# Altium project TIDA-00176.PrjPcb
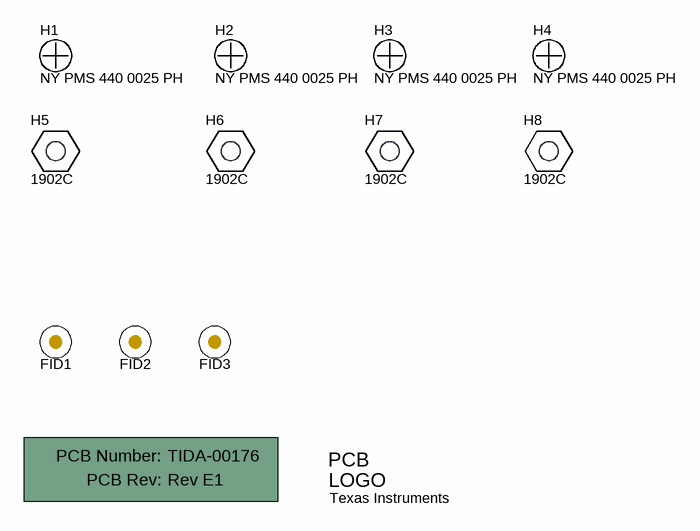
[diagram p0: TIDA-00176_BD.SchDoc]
CopyrightYear: 2015; EVM_Orderable: N/A; PCB_Layout: Stauder; PCB_Rev: Rev E1; PRJ_Customer: Public Release; PRJ_Engineer: Stauder/Pizzolante/Staebler; PRJ_Number: TIDA-00176; PRJ_Title: Interface to a SinCos Position Encoder; SCH_Rev: E1; TechSupport: http://www.ti.com/support; TID: 00176
4 sheets, 235 parts. Net scope: global (net labels, ports and power ports of the same name join across sheets).
Board file: TID.PcbDoc
Sheets:
  TIDA-00176_BD.SchDoc
  TIDA-00176_PS.SchDoc
  TIDA-00176_SCHS.SchDoc
  TIDA-00176_SCLS.SchDoc

## Sheet TIDA-00176_BD.SchDoc
size 431 x 279 mm; Date: Not shown in title block; ApprovedBy: Not shown in title block; CheckedBy: Not shown in title block; Author: Not shown in title block; CompanyName: Not shown in title block; Engineer: Not shown in title block; Organization: Not shown in title block; Address1: Not shown in title block; Address2: Not shown in title block; Address3: Not shown in title block; Address4: Not shown in title block; DocumentNumber: 1; Revision: Use project parameter SCH_Rev; SheetNumber: 3; SheetTotal: 3; PageSetup: Record=PageOptions¦CenterHorizontal=True¦CenterVertical=True¦PrintScale=1.00¦XCorrection=1.00¦YCorrection=1.00¦PrintKind=0¦BorderSize=5000000¦LeftOffset=0¦BottomOffset=0¦Orientation=2¦PaperLength=1000¦PaperWidth=1000¦Scale=100¦PaperSource=15¦PrintQuality=600¦MediaType=1¦DitherType=10¦PaperKind=Letter¦PrintScaleMode=1

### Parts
!PCB1  Printed Circuit Board  (value not drawn)  (mechanical)
FID1  Fiducial  [Fiducial10-20]  (value not drawn)
FID2  Fiducial  [Fiducial10-20]  (value not drawn)
FID3  Fiducial  [Fiducial10-20]  (value not drawn)
H1  NY PMS 440 0025 PH  [NY PMS 440 0025 PH]
H2  NY PMS 440 0025 PH  [NY PMS 440 0025 PH]
H3  NY PMS 440 0025 PH  [NY PMS 440 0025 PH]
H4  NY PMS 440 0025 PH  [NY PMS 440 0025 PH]
H5  1902C  [Keystone_1902C]
H6  1902C  [Keystone_1902C]
H7  1902C  [Keystone_1902C]
H8  1902C  [Keystone_1902C]
Logo1  Texas Instruments  [TI_Stacked_Overlay_Small]  (no BOM)

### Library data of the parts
!PCB1 = PCB: Manufacturer: Any; PartNumber: TIDA-00176; SymbolCreator: a0412235
FID1-FID3 = Fiducial: Fiducial mark.  There is nothing to buy or mount.; SymbolCreator: codlsc
H1-H4 = NY PMS 440 0025 PH: Machine Screw, Round, #4-40 x 1/4, Nylon, Philips panhead; Manufacturer: B&F Fastener Supply; CompType: Hardware; SymbolCreator: codlsc; U/M: EA
H5-H8 = 1902C: Standoff, Hex, 0.5"L #4-40 Nylon; Manufacturer: Keystone; CompType: Hardware
Logo1 = TI_Logo: Texas Instrument Corporate Signature; SymbolCreator: a0412235

## Sheet TIDA-00176_PS.SchDoc
size 431 x 279 mm; Date: Not shown in title block; ApprovedBy: Not shown in title block; CheckedBy: Not shown in title block; Author: Not shown in title block; CompanyName: Not shown in title block; Engineer: Not shown in title block; Organization: Not shown in title block; Address1: Not shown in title block; Address2: Not shown in title block; Address3: Not shown in title block; Address4: Not shown in title block; DocumentNumber: 1; Revision: Use project parameter SCH_Rev; SheetNumber: 2; SheetTotal: 3; PageSetup: Record=PageOptions¦CenterHorizontal=True¦CenterVertical=True¦PrintScale=0.66¦XCorrection=1.00¦YCorrection=1.00¦PrintKind=0¦BorderSize=5000000¦LeftOffset=0¦BottomOffset=0¦Orientation=2¦PaperLength=2970¦PaperWidth=2100¦Scale=100¦PaperSource=7¦PrintQuality=600¦MediaType=1¦DitherType=10¦PrintScaleMode=1¦PaperKind=A4¦PaperIndex=9
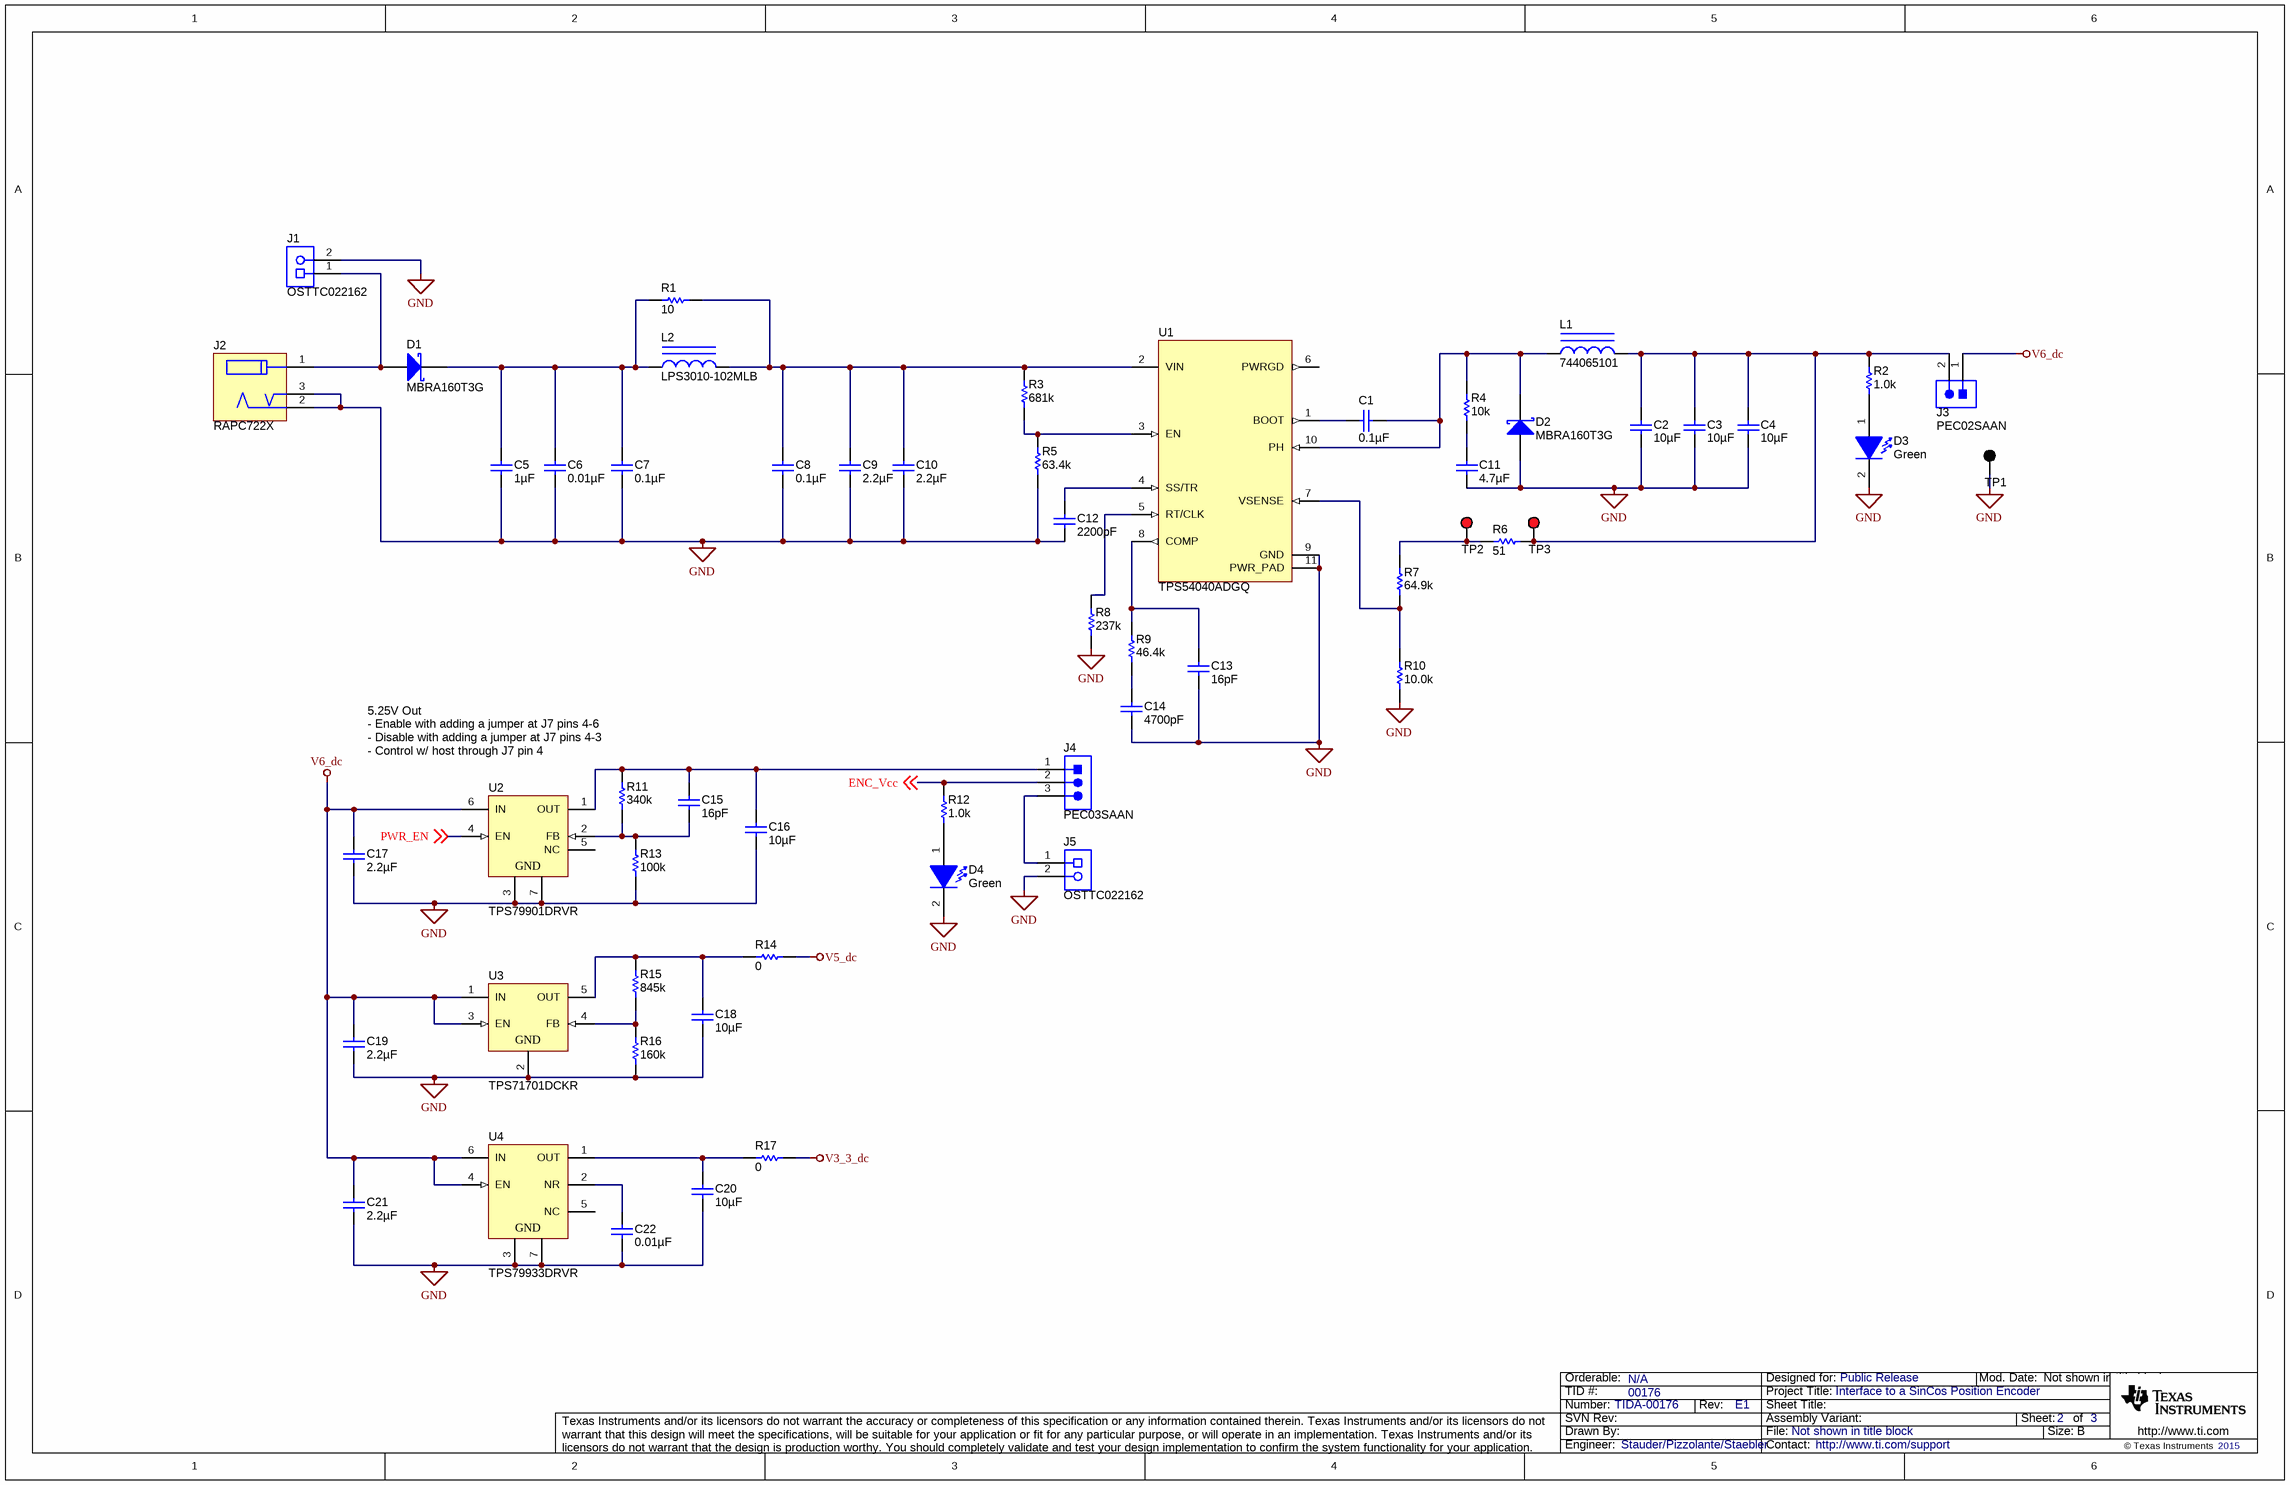
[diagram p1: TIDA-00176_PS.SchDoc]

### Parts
C1  ValueDisplayed: 0.1µF  [0603]  (hidden comment: GRM188R71H104KA93D)
C2  ValueDisplayed: 10µF  [1206_190]  (hidden comment: CGA5L3X5R1H106K160AB)
C3  ValueDisplayed: 10µF  [1206_190]  (hidden comment: CGA5L3X5R1H106K160AB)
C4  ValueDisplayed: 10µF  [1206_190]  (hidden comment: CGA5L3X5R1H106K160AB)
C5  ValueDisplayed: 1µF  [0805_HV]  (hidden comment: GRM21BR71H105KA12L)
C6  ValueDisplayed: 0.01µF  [0805_HV]  (hidden comment: GRM216R71H103KA01D)
C7  ValueDisplayed: 0.1µF  [0603]  (hidden comment: GRM188R71H104KA93D)
C8  ValueDisplayed: 0.1µF  [0603]  (hidden comment: GRM188R71H104KA93D)
C9  ValueDisplayed: 2.2µF  [1206]  (hidden comment: GRM31CR61H225KA88L)
C10  ValueDisplayed: 2.2µF  [1206]  (hidden comment: GRM31CR61H225KA88L)
C11  ValueDisplayed: 4.7µF  [0805_HV]  (hidden comment: C2012X5R1H475K125AB)
C12  ValueDisplayed: 2200pF  [0402]  (hidden comment: GRM155R61C222KA01D)
C13  ValueDisplayed: 16pF  [0402]  (hidden comment: GRM1555C1H160JA01D)
C14  ValueDisplayed: 4700pF  [0402]  (hidden comment: GRM155R71C472KA01D)
C15  ValueDisplayed: 16pF  [0402]  (hidden comment: GRM1555C1H160JA01D)
C16  ValueDisplayed: 10µF  [0805_HV]  (hidden comment: GRM219R61C106KA73D)
C17  ValueDisplayed: 2.2µF  [0603]  (hidden comment: GRM188R61C225KE15D)
C18  ValueDisplayed: 10µF  [0805_HV]  (hidden comment: GRM219R61C106KA73D)
C19  ValueDisplayed: 2.2µF  [0603]  (hidden comment: GRM188R61C225KE15D)
C20  ValueDisplayed: 10µF  [0805_HV]  (hidden comment: GRM219R61C106KA73D)
C21  ValueDisplayed: 2.2µF  [0603]  (hidden comment: GRM188R61C225KE15D)
C22  ValueDisplayed: 0.01µF  [0603]  (hidden comment: GRM188R71C103KA01D)
D1  MBRA160T3G  [SMA]
D2  MBRA160T3G  [SMA]
D3  value Green  [LG L29K_GREEN]  (hidden comment: LG L29K-G2J1-24-Z)
D4  value Green  [LG L29K_GREEN]  (hidden comment: LG L29K-G2J1-24-Z)
J1  OSTTC022162  [On-Shore_OSTTC022162]
J2  RAPC722X  [CONN_RAPC722X]
J3  PEC02SAAN  [CONN_PEC02SAAN]
J4  PEC03SAAN  [CONN_PEC03SAAN]
J5  OSTTC022162  [On-Shore_OSTTC022162]
L1  744065101  [WE-TPC-XLH2]
L2  LPS3010-102MLB  [LPS3010]
R1  value 10  [0603]  (hidden comment: CRCW060310R0JNEAHP)
R2  ValueDisplayed: 1.0k  [0402]  (hidden comment: CRCW04021K00JNED)
R3  ValueDisplayed: 681k  [0402]  (hidden comment: CRCW0402681KFKED)
R4  value 10k  [0805_HV]  (hidden comment: CRCW080510K0JNEA)
R5  ValueDisplayed: 63.4k  [0402]  (hidden comment: CRCW040263K4FKED)
R6  value 51  [0603]  (hidden comment: CRCW060351R0JNEA)
R7  ValueDisplayed: 64.9k  [0402]  (hidden comment: CRCW040264K9FKED)
R8  ValueDisplayed: 237k  [0402]  (hidden comment: CRCW0402237KFKED)
R9  ValueDisplayed: 46.4k  [0402]  (hidden comment: CRCW040246K4FKED)
R10  ValueDisplayed: 10.0k  [0402]  (hidden comment: CRCW040210K0FKED)
R11  ValueDisplayed: 340k  [0402]  (hidden comment: CRCW0402340KFKED)
R12  ValueDisplayed: 1.0k  [0402]  (hidden comment: CRCW04021K00JNED)
R13  ValueDisplayed: 100k  [0402]  (hidden comment: CRCW0402100KJNED)
R14  ValueDisplayed: 0  [0402]  (hidden comment: CRCW04020000Z0ED)
R15  ValueDisplayed: 845k  [0402]  (hidden comment: CRCW0402845KFKED)
R16  ValueDisplayed: 160k  [0402]  (hidden comment: CRCW0402160KJNED)
R17  ValueDisplayed: 0  [0402]  (hidden comment: CRCW04020000Z0ED)
TP1  5001  [Keystone5001]  (value not drawn)
TP2  5000  [Keystone5000]  (value not drawn)
TP3  5000  [Keystone5000]  (value not drawn)
U1  TPS54040ADGQ  [DGQ0010D_N]
U2  TPS79901DRVR  [DRV0006A]
U3  TPS71701DCKR  [DCK0005A_N]
U4  TPS79933DRVR  [DRV0006A]

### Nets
GND: C2.2 C3.2 C4.2 C5.2 C6.2 C7.2 C8.2 C9.2 C10.2 C11.2 C12.2 C13.2 C14.2 C16.2 C17.2 C18.2 C19.2 C20.2 C21.2 C22.2 D2.2(A) D3.2(K) D4.2(K) J1.2 J2.2 J2.3 J5.2 R5.1 R8.1 R10.1 R13.1 R16.1 TP1.1 U1.9(GND) U1.11(PWR_PAD) U2.3(GND) U2.7(GND) U3.2(GND) U4.3(GND) U4.7(GND)
V3_3_dc: R17.2
V5_dc: R14.2
V6_dc: C17.1 C19.1 C21.1 J3.1 U2.6(IN) U3.1(IN) U3.3(EN) U4.4(EN) U4.6(IN)
ENC_Vcc: J4.2 R12.2 ; off-sheet ENC_Vcc
PWR_EN: U2.4(EN) ; off-sheet PWR_EN
NetC1_1: C1.1 D2.1(K) L1.1 R4.2 U1.10(PH)
NetC1_2: C1.2 U1.1(BOOT)
NetC2_1: C2.1 C3.1 C4.1 J3.2 L1.2 R2.2 R6.1 TP3.1
NetC5_1: C5.1 C6.1 C7.1 D1.1(K) L2.1 R1.1
NetC8_1: C8.1 C9.1 C10.1 L2.2 R1.2 R3.2 U1.2(VIN)
NetC11_1: C11.1 R4.1
NetC12_1: C12.1 U1.4(SS/TR)
NetC13_1: C13.1 R9.2 U1.8(COMP)
NetC14_1: C14.1 R9.1
NetC15_1: C15.1 C16.1 J4.1 R11.2 U2.1(OUT)
NetC15_2: C15.2 R11.1 R13.2 U2.2(FB)
NetC18_1: C18.1 R14.1 R15.2 U3.5(OUT)
NetC20_1: C20.1 R17.1 U4.1(OUT)
NetC22_1: C22.1 U4.2(NR)
NetD1_2: D1.2(A) J1.1 J2.1
NetD3_1: D3.1(A) R2.1
NetD4_1: D4.1(A) R12.1
NetJ4_3: J4.3 J5.1
NetR3_1: R3.1 R5.2 U1.3(EN)
NetR6_2: R6.2 R7.2 TP2.1
NetR7_1: R7.1 R10.2 U1.7(VSENSE)
NetR8_2: R8.2 U1.5(RT/CLK)
NetR15_1: R15.1 R16.2 U3.4(FB)

Not connected (* = marked no-connect by the designer): U1 6(PWRGD); U2 5(NC); U4 5(NC)

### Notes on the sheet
- (near R11) 5.25V Out
  - Enable with adding a jumper at J7 pins 4-6
  - Disable with adding a jumper at J7 pins 4-3
  - Control w/ host through J7 pin 4

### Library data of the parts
C1 C7 C8 = GRM188R71H104KA93D: CAP, CERM, 0.1 µF, 50 V, +/- 10%, X7R, 0603; Manufacturer: MuRata; Polarized: N; CompType: Capacitor; Value: 0.1uF; U/M: EA; Cap_F: 0.0000001; Tolerance_%: 10; Value1: Unknown; VDC_V: 50; Value2: 50V; TaMin_C: -55; TaMax_C: 125
C2-C4 = CGA5L3X5R1H106K160AB: CAP, CERM, 10 µF, 50 V, +/- 10%, X5R, 1206_190; Manufacturer: TDK; Polarized: N; CompType: Capacitor; Value: 10uF; U/M: EA; Cap_F: 0.00001; Tolerance_%: 10; Value1: Unknown; VDC_V: 50; Value2: 50V; TaMin_C: -55; TaMax_C: 85
C5 = GRM21BR71H105KA12L: CAP, CERM, 1 µF, 50 V, +/- 10%, X7R, 0805; Manufacturer: MuRata; Polarized: N; CompType: Capacitor; Value: 1uF; U/M: EA; Cap_F: 0.000001; Tolerance_%: 10; Value1: Unknown; VDC_V: 50; Value2: 50V; TaMin_C: -55; TaMax_C: 125; Cap_Case: 0805
C6 = GRM216R71H103KA01D: CAP, CERM, 0.01 µF, 50 V, +/- 10%, X7R, 0805; Manufacturer: MuRata; Polarized: N; CompType: Capacitor; Value: 0.01uF; U/M: EA; Cap_F: 0.00000001; Tolerance_%: 10; Value1: Unknown; VDC_V: 50; Value2: 50V; TaMin_C: -55; TaMax_C: 125; Cap_Case: 0805
C9 C10 = GRM31CR61H225KA88L: CAP, CERM, 2.2uF, 50V, +/-10%, X5R, 1206; Manufacturer: MuRata; Polarized: N; CompType: Capacitor; U/M: EA; Cap_F: 0.0000022; Tolerance_%: 10; Value1: Unknown; VDC_V: 50; TaMin_C: -55; TaMax_C: 85
C11 = C2012X5R1H475K125AB: CAP, CERM, 4.7 µF, 50 V, +/- 10%, X5R, 0805; Manufacturer: TDK; Polarized: N; CompType: Capacitor; Value: 4.7uF; U/M: EA; Cap_F: 0.0000047; Tolerance_%: 10; Value1: Unknown; VDC_V: 50; Value2: 50V; TaMin_C: -55; TaMax_C: 85; Cap_Case: 0805
C12 = GRM155R61C222KA01D: CAP, CERM, 2200 pF, 16 V, +/- 10%, X5R, 0402; Manufacturer: MuRata; Polarized: N; CompType: Capacitor; Value: 2200pF; U/M: EA; Cap_F: 0.0000000022; Tolerance_%: 10; Value1: Unknown; VDC_V: 16; Value2: 16V; TaMin_C: -55; TaMax_C: 85
C13 C15 = GRM1555C1H160JA01D: CAP, CERM, 16 pF, 50 V, +/- 5%, C0G/NP0, 0402; Manufacturer: MuRata; Polarized: N; CompType: Capacitor; Value: 16pF; U/M: EA; Cap_F: 0.000000000016; Tolerance_%: 5; Value1: Unknown; VDC_V: 50; Value2: 50V; TaMin_C: -55; TaMax_C: 125
C14 = GRM155R71C472KA01D: CAP, CERM, 4700 pF, 16 V, +/- 10%, X7R, 0402; Manufacturer: MuRata; Polarized: N; CompType: Capacitor; Value: 4700pF; U/M: EA; Cap_F: 0.0000000047; Tolerance_%: 10; Value1: Unknown; VDC_V: 16; Value2: 16V; TaMin_C: -55; TaMax_C: 125
C16 C18 C20 = GRM219R61C106KA73D: CAP, CERM, 10 µF, 16 V, +/- 10%, X5R, 0805; Manufacturer: MuRata; Polarized: N; CompType: Capacitor; Value: 10uF; U/M: EA; Cap_F: 0.00001; Tolerance_%: 10; Value1: Unknown; VDC_V: 16; Value2: 16V; TaMin_C: -55; TaMax_C: 85; Cap_Case: 0805
C17 C19 C21 = GRM188R61C225KE15D: CAP, CERM, 2.2 µF, 16 V, +/- 10%, X5R, 0603; Manufacturer: MuRata; Polarized: N; CompType: Capacitor; Value: 2.2uF; U/M: EA; Cap_F: 0.0000022; Tolerance_%: 10; Value1: Unknown; VDC_V: 16; Value2: 16V; TaMin_C: -55; TaMax_C: 85
C22 = GRM188R71C103KA01D: CAP, CERM, 0.01 µF, 16 V, +/- 10%, X7R, 0603; Manufacturer: MuRata; Polarized: N; CompType: Capacitor; Value: 0.01uF; U/M: EA; Cap_F: 0.00000001; Tolerance_%: 10; Value1: Unknown; VDC_V: 16; Value2: 16V; TaMin_C: -55; TaMax_C: 125
D1 D2 = MBRA160T3G: Diode, Schottky, 60V, 1A, SMA; Manufacturer: ON Semiconductor; U/M: EA; Vf_V: 0.51; Value2: 0.51V; Io_A: 1; Vr_V: 60; TJmax_C: 150; RJC_CperW: 35
D3 D4 = LG L29K-G2J1-24-Z: LED, Green, SMD; Manufacturer: OSRAM; Vf_V: 1.7; Value2: 1.7V; Io_A: 0.002; Tjmax_C: 110; Value1: W; U/M: EA
J1 J5 = OSTTC022162: Terminal Block, 2-pole, 200mil, TH; Manufacturer: On-Shore Technology; SymbolCreator: a0412235; U/M: EA
J2 = RAPC722X: Power Jack, mini, 2.1mm OD, R/A, TH; Manufacturer: Switchcraft; SymbolCreator: a0799628; U/M: EA
J3 = PEC02SAAN: Header, 100mil, 2x1, Tin, TH; Manufacturer: Sullins Connector Solutions; SymbolCreator: a0412235; U/M: EA
J4 = PEC03SAAN: Header, 100mil, 3x1, Tin, TH; Manufacturer: Sullins Connector Solutions; SymbolCreator: a0799628; U/M: EA
L1 = 744065101: Inductor, Shielded Drum Core, Ferrite, 100 µH, 0.9 A, 0.33 ohm, SMD; Manufacturer: Wurth Elektronik eiSos; Value: 100uH; Ind_H: 100.0E-6; ValueDisplayed: 100µH; Imax_A: 0.9; Irms: 1A @ 30C rise; Isat: 0.9A @ 35% inductance drop; DCR_ohm: 0.33; Value2: 0.9A
L2 = LPS3010-102MLB: Inductor, Shielded Drum Core, Ferrite, 1 µH, 1.5 A, 0.09 ohm, SMD; Manufacturer: Coilcraft; Value: 1uH; Ind_H: 1.0E-6; ValueDisplayed: 1µH; Imax_A: 1.5; Irms: 1.5A @ 40C rise; Isat: 1.6A @ 30% inductance drop; DCR_ohm: 0.09; Value2: 1.5A
R1 = CRCW060310R0JNEAHP: RES, 10 ohm, 5%, 0.25W, 0603; Manufacturer: Vishay-Dale; CompType: Resistor; Value_Code: 10R0; Tolerance_%: 5; Power_W: 0.25; VDC_V: 75; TempCo: 200 ppm/C; EIA_Code: E24; U/M: EA
R2 R12 = CRCW04021K00JNED: RES, 1.0 k, 5%, 0.063 W, 0402; Manufacturer: Vishay-Dale; CompType: Resistor; Value: 1.0k; Res_ohm: 1000; Value_Code: 1k00; Tolerance_%: 5; Power_W: 0.063; Value2: 0.063W; VDC_V: 50; TempCo: 200 ppm/C; EIA_Code: E24; U/M: EA
R3 = CRCW0402681KFKED: RES, 681 k, 1%, 0.063 W, 0402; Manufacturer: Vishay-Dale; CompType: Resistor; Value: 681k; Res_ohm: 681000; Tolerance_%: 1; Power_W: 0.063; Value2: 0.063W; VDC_V: 50; TempCo: 100 ppm/C; EIA_Code: E96; U/M: EA
R4 = CRCW080510K0JNEA: RES, 10k ohm, 5%, 0.125W, 0805; Manufacturer: Vishay-Dale; CompType: Resistor; Res_ohm: 10000; Value_Code: 10k0; Tolerance_%: 5; Power_W: 0.125; VDC_V: 150; TempCo: 200 ppm/C; EIA_Code: E24; U/M: EA
R5 = CRCW040263K4FKED: RES, 63.4 k, 1%, 0.063 W, 0402; Manufacturer: Vishay-Dale; CompType: Resistor; Value: 63.4k; Res_ohm: 63400; Value_Code: 63k4; Tolerance_%: 1; Power_W: 0.063; Value2: 0.063W; VDC_V: 50; TempCo: 100 ppm/C; EIA_Code: E96; U/M: EA
R6 = CRCW060351R0JNEA: RES, 51 ohm, 5%, 0.1W, 0603; Manufacturer: Vishay-Dale; CompType: Resistor; Value_Code: 51R0; Tolerance_%: 5; Power_W: 0.1; VDC_V: 75; TempCo: 200 ppm/C; EIA_Code: E24; U/M: EA
R7 = CRCW040264K9FKED: RES, 64.9 k, 1%, 0.063 W, 0402; Manufacturer: Vishay-Dale; CompType: Resistor; Value: 64.9k; Res_ohm: 64900; Value_Code: 64k9; Tolerance_%: 1; Power_W: 0.063; Value2: 0.063W; VDC_V: 50; TempCo: 100 ppm/C; EIA_Code: E96; U/M: EA
R8 = CRCW0402237KFKED: RES, 237 k, 1%, 0.063 W, 0402; Manufacturer: Vishay-Dale; CompType: Resistor; Value: 237k; Res_ohm: 237000; Tolerance_%: 1; Power_W: 0.063; Value2: 0.063W; VDC_V: 50; TempCo: 100 ppm/C; EIA_Code: E96; U/M: EA
R9 = CRCW040246K4FKED: RES, 46.4 k, 1%, 0.063 W, 0402; Manufacturer: Vishay-Dale; CompType: Resistor; Value: 46.4k; Res_ohm: 46400; Value_Code: 46k4; Tolerance_%: 1; Power_W: 0.063; Value2: 0.063W; VDC_V: 50; TempCo: 100 ppm/C; EIA_Code: E96; U/M: EA
R10 = CRCW040210K0FKED: RES, 10.0 k, 1%, 0.063 W, 0402; Manufacturer: Vishay-Dale; CompType: Resistor; Value: 10.0k; Res_ohm: 10000; Value_Code: 10k0; Tolerance_%: 1; Power_W: 0.063; Value2: 0.063W; VDC_V: 50; TempCo: 100 ppm/C; EIA_Code: E96; U/M: EA
R11 = CRCW0402340KFKED: RES, 340 k, 1%, 0.063 W, 0402; Manufacturer: Vishay-Dale; CompType: Resistor; Value: 340k; Res_ohm: 340000; Tolerance_%: 1; Power_W: 0.063; Value2: 0.063W; VDC_V: 50; TempCo: 100 ppm/C; EIA_Code: E96; U/M: EA
R13 = CRCW0402100KJNED: RES, 100 k, 5%, 0.063 W, 0402; Manufacturer: Vishay-Dale; CompType: Resistor; Value: 100k; Res_ohm: 100000; Tolerance_%: 5; Power_W: 0.063; Value2: 0.063W; VDC_V: 50; TempCo: 200 ppm/C; EIA_Code: E24; U/M: EA
R14 R17 = CRCW04020000Z0ED: RES, 0, 5%, 0.063 W, 0402; Manufacturer: Vishay-Dale; CompType: Resistor; Value: 0; Value_Code: 0000; Tolerance_%: 5; Power_W: 0.063; Value2: 0.063W; VDC_V: 50; TempCo: 200 ppm/C; EIA_Code: E24; U/M: EA
R15 = CRCW0402845KFKED: RES, 845 k, 1%, 0.063 W, 0402; Manufacturer: Vishay-Dale; CompType: Resistor; Value: 845k; Res_ohm: 845000; Tolerance_%: 1; Power_W: 0.063; Value2: 0.063W; VDC_V: 50; TempCo: 100 ppm/C; EIA_Code: E96; U/M: EA
R16 = CRCW0402160KJNED: RES, 160 k, 5%, 0.063 W, 0402; Manufacturer: Vishay-Dale; CompType: Resistor; Value: 160k; Res_ohm: 160000; Tolerance_%: 5; Power_W: 0.063; Value2: 0.063W; VDC_V: 50; TempCo: 200 ppm/C; EIA_Code: E24; U/M: EA
TP1 = 5001: Test Point, Miniature, Black, TH; Manufacturer: Keystone; CompType: Test Point Loop; U/M: EA
TP2 TP3 = 5000: Test Point, Miniature, Red, TH; Manufacturer: Keystone; CompType: Test Point Loop; U/M: EA
U1 = TPS54040ADGQ: 0.5 A, 42 V Step Down DC/DC Converter with Eco-mode, DGQ0010D; Manufacturer: Texas Instruments; SymbolCreator: a0411947; CompType: IC; U/M: EA
U2 = TPS79901DRVR: Single Output High PSRR LDO, 200 mA, Adjustable 1.2 to 6.5 V Output, 2.7 to 6.5 V Input, with Low IQ, 6-pin SON (DRV), -40 to 85 degC, Green (RoHS & no Sb/Br); Manufacturer: Texas Instruments; Alternate Manufacturer: None; Alternate PartNumber: Equivalent; Accuracy(%): 2; Iout(Max)(A): 0.2; Iq(Typ)(mA): 0.04; Rating: Catalog; SubFamily: Single Channel LDO; Vdo(Typ)(mV): 90; Vin(Max)(V): 6.5; Vin(Min)(V): 2.7; Vout Adj(Min)(V): 1.2
U3 = TPS71701DCKR: Single Output LDO, 150 mA, Adjustable 0.9 to 6.2 V Output, 2.5 to 6.5 V Input, with High-Bandwidth PSRR, 5-pin SC70 (DCK), -40 to 125 degC, Green (RoHS & no Sb/Br); Manufacturer: Texas Instruments; Alternate Manufacturer: None; Alternate PartNumber: Equivalent; Accuracy(%): 3; Iout(Max)(A): 0.15; Iq(Typ)(mA): 0.05; SubFamily: Single Channel LDO; Vdo(Typ)(mV): 170; Vin(Max)(V): 6.5; Vin(Min)(V): 2.5; Vout Adj(Max)(V): 6.2; Vout Adj(Min)(V): 0.9
U4 = TPS79933DRVR: Single Output High PSRR LDO, 200 mA, Fixed 3.3 V Output, 2.7 to 6.5 V Input, with Low IQ, 6-pin SON (DRV), -40 to 85 degC, Green (RoHS & no Sb/Br); Manufacturer: Texas Instruments; Alternate Manufacturer: None; Alternate PartNumber: Equivalent; Accuracy(%): 2; Fixed Output Options(V): 3.3; Iout(Max)(A): 0.2; Iq(Typ)(mA): 0.04; Rating: Catalog; SubFamily: Single Channel LDO; Vdo(Typ)(mV): 90; Vin(Max)(V): 6.5; Vin(Min)(V): 2.7

## Sheet TIDA-00176_SCHS.SchDoc
size 431 x 279 mm; Date: Not shown in title block; ApprovedBy: Not shown in title block; CheckedBy: Not shown in title block; Author: Not shown in title block; CompanyName: Not shown in title block; Engineer: Not shown in title block; Organization: Not shown in title block; Address1: Not shown in title block; Address2: Not shown in title block; Address3: Not shown in title block; Address4: Not shown in title block; DocumentNumber: 1; Revision: Use project parameter SCH_Rev; SheetNumber: 2; SheetTotal: 3; PageSetup: Record=PageOptions¦CenterHorizontal=True¦CenterVertical=True¦PrintScale=0.66¦XCorrection=1.00¦YCorrection=1.00¦PrintKind=0¦BorderSize=5000000¦LeftOffset=0¦BottomOffset=0¦Orientation=2¦PaperLength=2970¦PaperWidth=2100¦Scale=100¦PaperSource=7¦PrintQuality=600¦MediaType=1¦DitherType=10¦PrintScaleMode=1¦PaperKind=A4¦PaperIndex=9
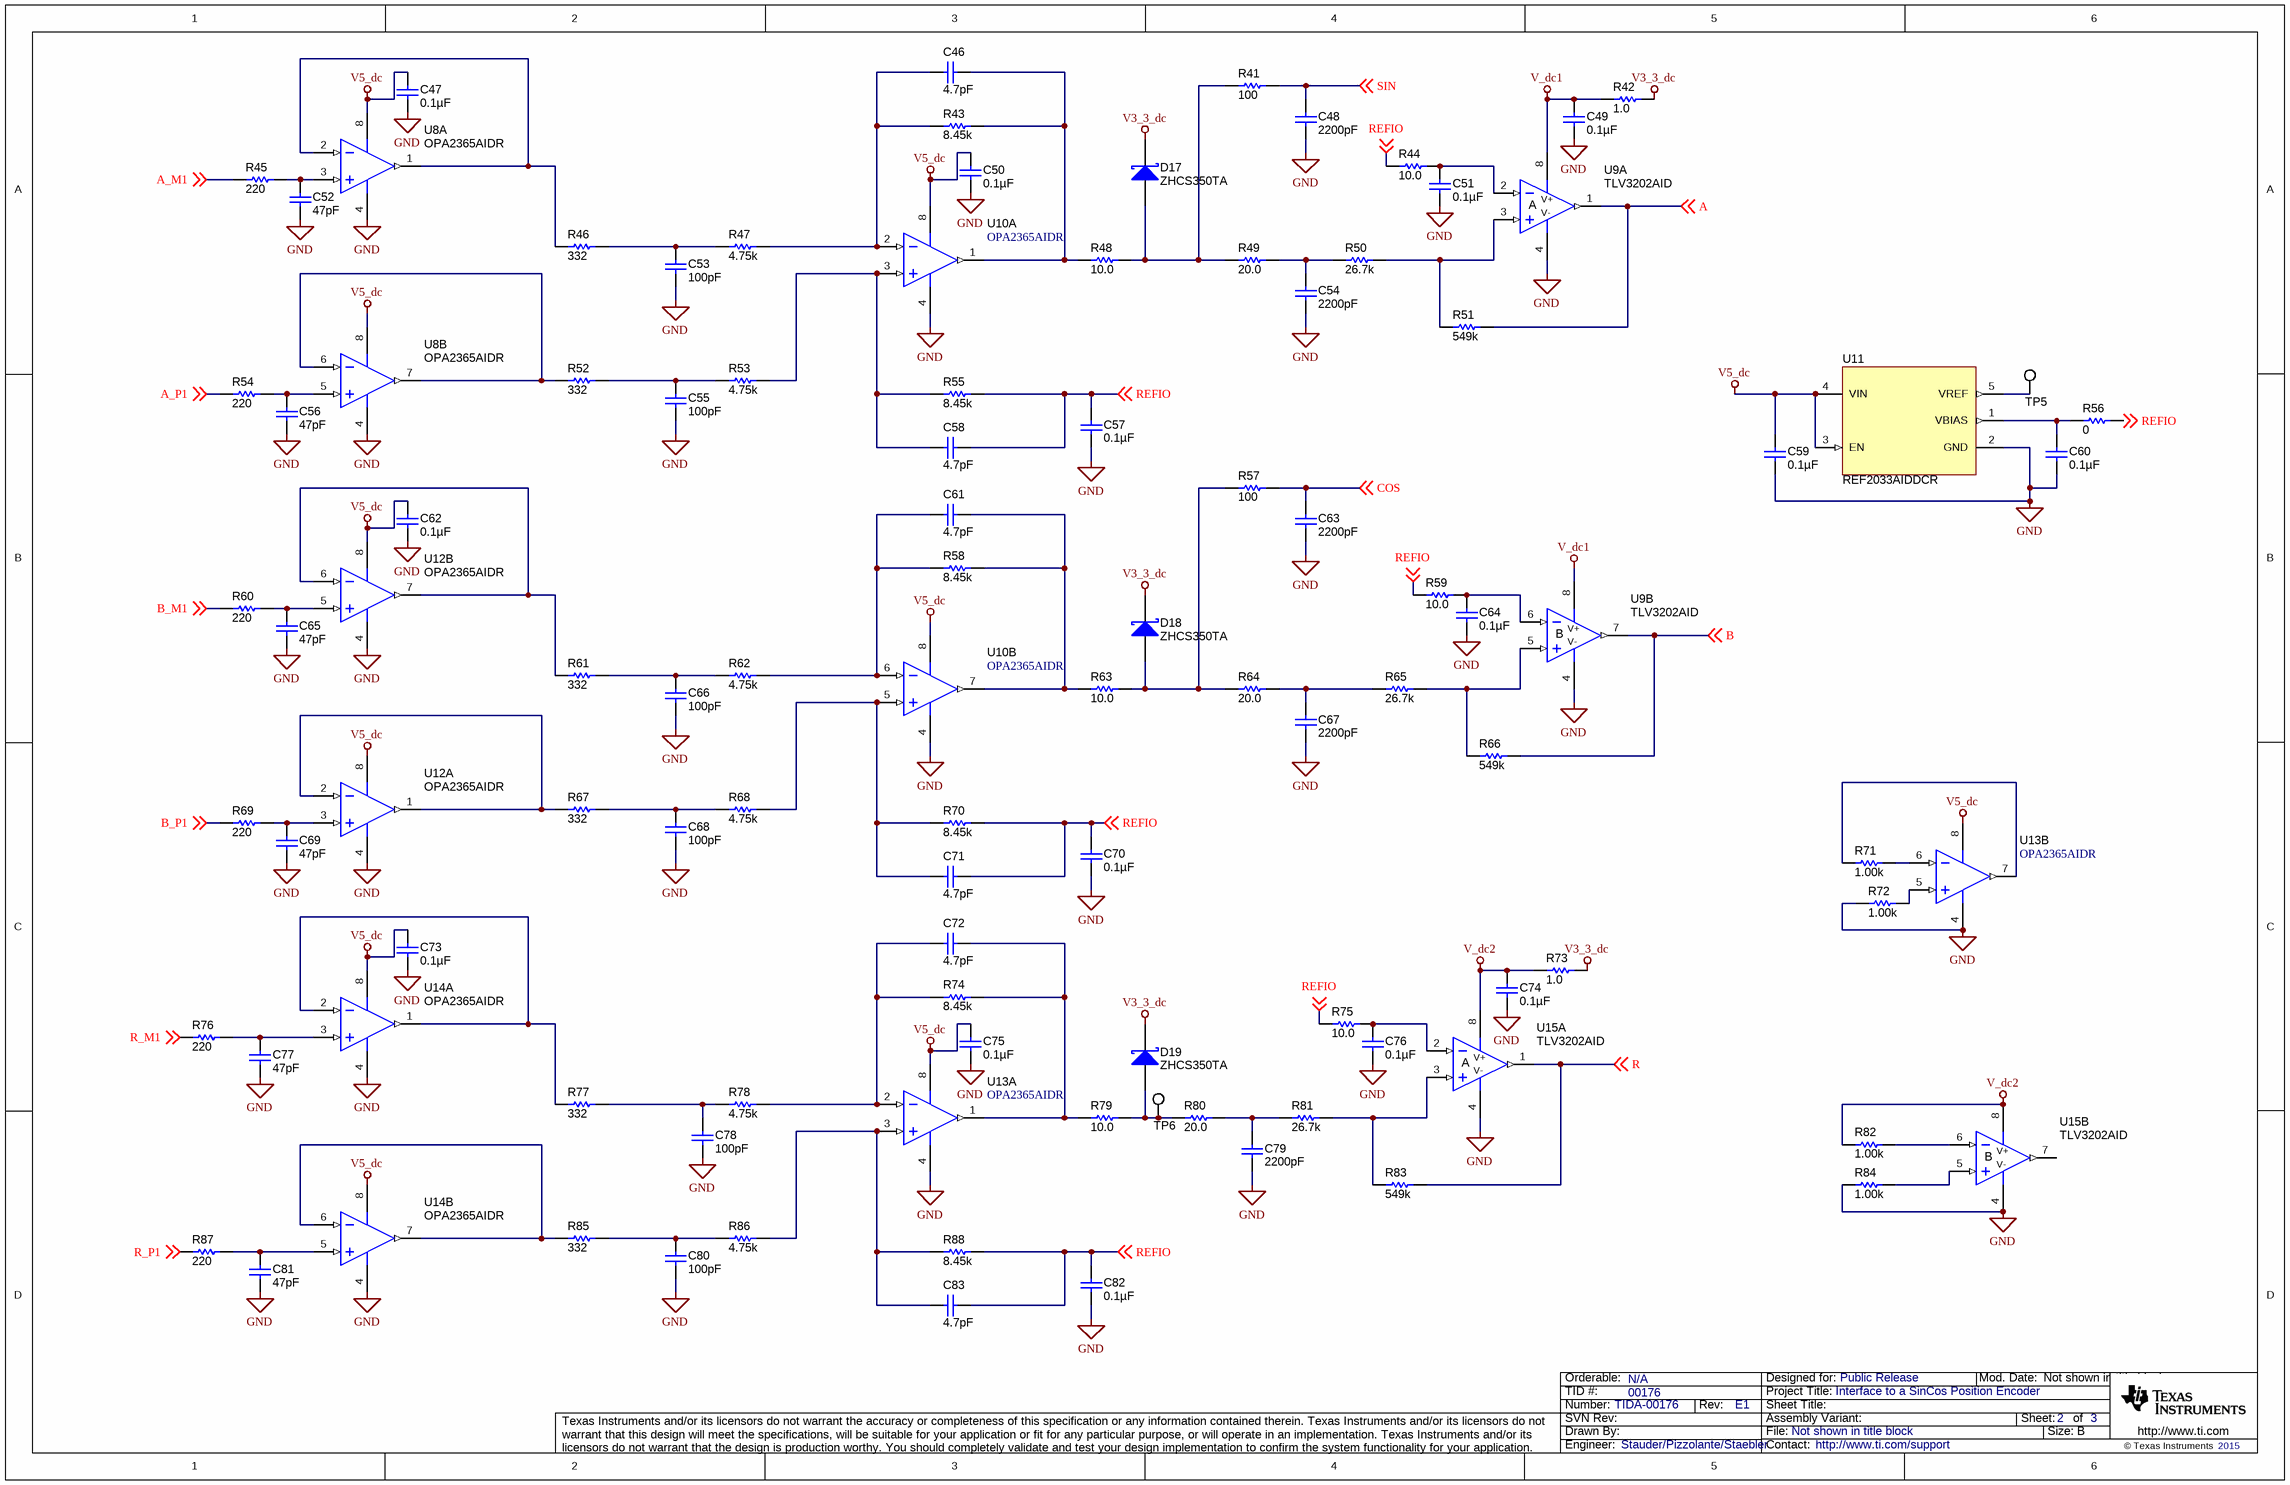
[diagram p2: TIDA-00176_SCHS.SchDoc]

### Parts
C46  ValueDisplayed: 4.7pF  [0402]  (hidden comment: GRM1555C1H4R7WA01D)
C47  ValueDisplayed: 0.1µF  [0603]  (hidden comment: GRM188R71C104KA01D)
C48  ValueDisplayed: 2200pF  [0603]  (hidden comment: GRM1885C1H222JA01D)
C49  ValueDisplayed: 0.1µF  [0603]  (hidden comment: GRM188R71C104KA01D)
C50  ValueDisplayed: 0.1µF  [0603]  (hidden comment: GRM188R71C104KA01D)
C51  ValueDisplayed: 0.1µF  [0402]  (hidden comment: GRM155R71C104KA88D)
C52  ValueDisplayed: 47pF  [0402]  (hidden comment: GRM1555C1E470JA01D)
C53  ValueDisplayed: 100pF  [0402]  (hidden comment: GRM1535C1H101JDD5D)
C54  ValueDisplayed: 2200pF  [0603]  (hidden comment: GRM1885C1H222JA01D)
C55  ValueDisplayed: 100pF  [0402]  (hidden comment: GRM1535C1H101JDD5D)
C56  ValueDisplayed: 47pF  [0402]  (hidden comment: GRM1555C1E470JA01D)
C57  ValueDisplayed: 0.1µF  [0402]  (hidden comment: GRM155R71C104KA88D)
C58  ValueDisplayed: 4.7pF  [0402]  (hidden comment: GRM1555C1H4R7WA01D)
C59  ValueDisplayed: 0.1µF  [0603]  (hidden comment: GRM188R71C104KA01D)
C60  ValueDisplayed: 0.1µF  [0603]  (hidden comment: GRM188R71C104KA01D)
C61  ValueDisplayed: 4.7pF  [0402]  (hidden comment: GRM1555C1H4R7WA01D)
C62  ValueDisplayed: 0.1µF  [0603]  (hidden comment: GRM188R71C104KA01D)
C63  ValueDisplayed: 2200pF  [0603]  (hidden comment: GRM1885C1H222JA01D)
C64  ValueDisplayed: 0.1µF  [0402]  (hidden comment: GRM155R71C104KA88D)
C65  ValueDisplayed: 47pF  [0402]  (hidden comment: GRM1555C1E470JA01D)
C66  ValueDisplayed: 100pF  [0402]  (hidden comment: GRM1535C1H101JDD5D)
C67  ValueDisplayed: 2200pF  [0603]  (hidden comment: GRM1885C1H222JA01D)
C68  ValueDisplayed: 100pF  [0402]  (hidden comment: GRM1535C1H101JDD5D)
C69  ValueDisplayed: 47pF  [0402]  (hidden comment: GRM1555C1E470JA01D)
C70  ValueDisplayed: 0.1µF  [0402]  (hidden comment: GRM155R71C104KA88D)
C71  ValueDisplayed: 4.7pF  [0402]  (hidden comment: GRM1555C1H4R7WA01D)
C72  ValueDisplayed: 4.7pF  [0402]  (hidden comment: GRM1555C1H4R7WA01D)
C73  ValueDisplayed: 0.1µF  [0603]  (hidden comment: GRM188R71C104KA01D)
C74  ValueDisplayed: 0.1µF  [0603]  (hidden comment: GRM188R71C104KA01D)
C75  ValueDisplayed: 0.1µF  [0603]  (hidden comment: GRM188R71C104KA01D)
C76  ValueDisplayed: 0.1µF  [0402]  (hidden comment: GRM155R71C104KA88D)
C77  ValueDisplayed: 47pF  [0402]  (hidden comment: GRM1555C1E470JA01D)
C78  ValueDisplayed: 100pF  [0402]  (hidden comment: GRM1535C1H101JDD5D)
C79  ValueDisplayed: 2200pF  [0603]  (hidden comment: GRM1885C1H222JA01D)
C80  ValueDisplayed: 100pF  [0402]  (hidden comment: GRM1535C1H101JDD5D)
C81  ValueDisplayed: 47pF  [0402]  (hidden comment: GRM1555C1E470JA01D)
C82  ValueDisplayed: 0.1µF  [0402]  (hidden comment: GRM155R71C104KA88D)
C83  ValueDisplayed: 4.7pF  [0402]  (hidden comment: GRM1555C1H4R7WA01D)
D17  ZHCS350TA  [SOD-523]
D18  ZHCS350TA  [SOD-523]
D19  ZHCS350TA  [SOD-523]
R41  ValueDisplayed: 100  [0402]  (hidden comment: CRCW0402100RJNED)
R42  ValueDisplayed: 1.0  [0402]  (hidden comment: CRCW04021R00JNED)
R43  ValueDisplayed: 8.45k  [0402]  (hidden comment: ERA-2AEB8451X)
R44  ValueDisplayed: 10.0  [0402]  (hidden comment: CRCW040210R0FKED)
R45  ValueDisplayed: 220  [0402]  (hidden comment: CRCW0402220RJNED)
R46  ValueDisplayed: 332  [0402]  (hidden comment: CRCW0402332RFKED)
R47  ValueDisplayed: 4.75k  [0402]  (hidden comment: ERA-2AEB4751X)
R48  ValueDisplayed: 10.0  [0402]  (hidden comment: CRCW040210R0FKED)
R49  ValueDisplayed: 20.0  [0402]  (hidden comment: CRCW040220R0FKED)
R50  ValueDisplayed: 26.7k  [0402]  (hidden comment: CRCW040226K7FKED)
R51  ValueDisplayed: 549k  [0402]  (hidden comment: CRCW0402549KFKED)
R52  ValueDisplayed: 332  [0402]  (hidden comment: CRCW0402332RFKED)
R53  ValueDisplayed: 4.75k  [0402]  (hidden comment: ERA-2AEB4751X)
R54  ValueDisplayed: 220  [0402]  (hidden comment: CRCW0402220RJNED)
R55  ValueDisplayed: 8.45k  [0402]  (hidden comment: ERA-2AEB8451X)
R56  ValueDisplayed: 0  [0402]  (hidden comment: CRCW04020000Z0ED)
R57  ValueDisplayed: 100  [0402]  (hidden comment: CRCW0402100RJNED)
R58  ValueDisplayed: 8.45k  [0402]  (hidden comment: ERA-2AEB8451X)
R59  ValueDisplayed: 10.0  [0402]  (hidden comment: CRCW040210R0FKED)
R60  ValueDisplayed: 220  [0402]  (hidden comment: CRCW0402220RJNED)
R61  ValueDisplayed: 332  [0402]  (hidden comment: CRCW0402332RFKED)
R62  ValueDisplayed: 4.75k  [0402]  (hidden comment: ERA-2AEB4751X)
R63  ValueDisplayed: 10.0  [0402]  (hidden comment: CRCW040210R0FKED)
R64  ValueDisplayed: 20.0  [0402]  (hidden comment: CRCW040220R0FKED)
R65  ValueDisplayed: 26.7k  [0402]  (hidden comment: CRCW040226K7FKED)
R66  ValueDisplayed: 549k  [0402]  (hidden comment: CRCW0402549KFKED)
R67  ValueDisplayed: 332  [0402]  (hidden comment: CRCW0402332RFKED)
R68  ValueDisplayed: 4.75k  [0402]  (hidden comment: ERA-2AEB4751X)
R69  ValueDisplayed: 220  [0402]  (hidden comment: CRCW0402220RJNED)
R70  ValueDisplayed: 8.45k  [0402]  (hidden comment: ERA-2AEB8451X)
R71  ValueDisplayed: 1.00k  [0402]  (hidden comment: CRCW04021K00FKED)
R72  ValueDisplayed: 1.00k  [0402]  (hidden comment: CRCW04021K00FKED)
R73  ValueDisplayed: 1.0  [0402]  (hidden comment: CRCW04021R00JNED)
R74  ValueDisplayed: 8.45k  [0402]  (hidden comment: ERA-2AEB8451X)
R75  ValueDisplayed: 10.0  [0402]  (hidden comment: CRCW040210R0FKED)
R76  ValueDisplayed: 220  [0402]  (hidden comment: CRCW0402220RJNED)
R77  ValueDisplayed: 332  [0402]  (hidden comment: CRCW0402332RFKED)
R78  ValueDisplayed: 4.75k  [0402]  (hidden comment: ERA-2AEB4751X)
R79  ValueDisplayed: 10.0  [0402]  (hidden comment: CRCW040210R0FKED)
R80  ValueDisplayed: 20.0  [0402]  (hidden comment: CRCW040220R0FKED)
R81  ValueDisplayed: 26.7k  [0402]  (hidden comment: CRCW040226K7FKED)
R82  ValueDisplayed: 1.00k  [0402]  (hidden comment: CRCW04021K00FKED)
R83  ValueDisplayed: 549k  [0402]  (hidden comment: CRCW0402549KFKED)
R84  ValueDisplayed: 1.00k  [0402]  (hidden comment: CRCW04021K00FKED)
R85  ValueDisplayed: 332  [0402]  (hidden comment: CRCW0402332RFKED)
R86  ValueDisplayed: 4.75k  [0402]  (hidden comment: ERA-2AEB4751X)
R87  ValueDisplayed: 220  [0402]  (hidden comment: CRCW0402220RJNED)
R88  ValueDisplayed: 8.45k  [0402]  (hidden comment: ERA-2AEB8451X)
TP5  5002  [Keystone5002]  (value not drawn)
TP6  5002  [Keystone5002]  (value not drawn)
U8  OPA2365AIDR  [D0008A_N]  (parts A,B of 2)
U9  TLV3202AID  [D0008A_N]  (parts A,B of 2)
U10  OPA2365AIDR  [D0008A_N]  (parts A,B of 2)
U11  REF2033AIDDCR  [DDC0005A_N]
U12  OPA2365AIDR  [D0008A_N]  (parts A,B of 2)
U13  OPA2365AIDR  [D0008A_N]  (parts A,B of 2)
U14  OPA2365AIDR  [D0008A_N]  (parts A,B of 2)
U15  TLV3202AID  [D0008A_N]  (parts A,B of 2)

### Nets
GND: C47.1 C48.2 C49.1 C50.1 C51.2 C52.2 C53.2 C54.2 C55.2 C56.2 C57.2 C59.1 C60.1 C62.1 C63.2 C64.2 C65.2 C66.2 C67.2 C68.2 C69.2 C70.2 C73.1 C74.1 C75.1 C76.2 C77.2 C78.2 C79.2 C80.2 C81.2 C82.2 R72.1 R84.1 U8.4(V-) U9.4(V-) U10.4(V-) U11.2(GND) U12.4(V-) U13.4(V-) U14.4(V-) U15.4(V-)
V3_3_dc: D17.1(K) D18.1(K) D19.1(K) R42.2 R73.2
V5_dc: C47.2 C50.2 C59.2 C62.2 C73.2 C75.2 U8.8(V+) U10.8(V+) U11.3(EN) U11.4(VIN) U12.8(V+) U13.8(V+) U14.8(V+)
V_dc1: C49.2 R42.1 U9.8(V+)
V_dc2: C74.2 R73.1 R82.1 U15.8(V+)
A: R51.2 U9.1(OUT) ; off-sheet A
A_M1: R45.1 ; off-sheet A_M1
A_P1: R54.1 ; off-sheet A_P1
B: R66.2 U9.7(OUT) ; off-sheet B
B_M1: R60.1 ; off-sheet B_M1
B_P1: R69.1 ; off-sheet B_P1
COS: C63.1 R57.2 ; off-sheet COS
R: R83.2 U15.1(OUT) ; off-sheet R
R_M1: R76.1 ; off-sheet R_M1
R_P1: R87.1 ; off-sheet R_P1
REFIO: C57.1 C58.1 C70.1 C71.1 C82.1 C83.1 R44.1 R55.2 R56.2 R59.1 R70.2 R75.1 R88.2 ; off-sheet REFIO
SIN: C48.1 R41.2 ; off-sheet SIN
NetC46_1: C46.1 R43.2 R48.1 U10.1(VOUT_A)
NetC46_2: C46.2 R43.1 R47.2 U10.2(IN_A-)
NetC51_1: C51.1 R44.2 U9.2(IN-)
NetC52_1: C52.1 R45.2 U8.3(IN_A+)
NetC53_1: C53.1 R46.2 R47.1
NetC54_1: C54.1 R49.2 R50.1
NetC55_1: C55.1 R52.2 R53.1
NetC56_1: C56.1 R54.2 U8.5(IN_B+)
NetC58_2: C58.2 R53.2 R55.1 U10.3(IN_A+)
NetC60_2: C60.2 R56.1 U11.1(VBIAS)
NetC61_1: C61.1 R58.2 R63.1 U10.7(VOUT_B)
NetC61_2: C61.2 R58.1 R62.2 U10.6(IN_B-)
NetC64_1: C64.1 R59.2 U9.6(IN-)
NetC65_1: C65.1 R60.2 U12.5(IN_B+)
NetC66_1: C66.1 R61.2 R62.1
NetC67_1: C67.1 R64.2 R65.1
NetC68_1: C68.1 R67.2 R68.1
NetC69_1: C69.1 R69.2 U12.3(IN_A+)
NetC71_2: C71.2 R68.2 R70.1 U10.5(IN_B+)
NetC72_1: C72.1 R74.2 R79.1 U13.1(VOUT_A)
NetC72_2: C72.2 R74.1 R78.2 U13.2(IN_A-)
NetC76_1: C76.1 R75.2 U15.2(IN-)
NetC77_1: C77.1 R76.2 U14.3(IN_A+)
NetC78_1: C78.1 R77.2 R78.1
NetC79_1: C79.1 R80.2 R81.1
NetC80_1: C80.1 R85.2 R86.1
NetC81_1: C81.1 R87.2 U14.5(IN_B+)
NetC83_2: C83.2 R86.2 R88.1 U13.3(IN_A+)
NetD17_2: D17.2(A) R41.1 R48.2 R49.1
NetD18_2: D18.2(A) R57.1 R63.2 R64.1
NetD19_2: D19.2(A) R79.2 R80.1 TP6.1
NetR46_1: R46.1 U8.1(VOUT_A) U8.2(IN_A-)
NetR50_2: R50.2 R51.1 U9.3(IN+)
NetR52_1: R52.1 U8.6(IN_B-) U8.7(VOUT_B)
NetR61_1: R61.1 U12.6(IN_B-) U12.7(VOUT_B)
NetR65_2: R65.2 R66.1 U9.5(IN+)
NetR67_1: R67.1 U12.1(VOUT_A) U12.2(IN_A-)
NetR71_1: R71.1 U13.7(VOUT_B)
NetR71_2: R71.2 U13.6(IN_B-)
NetR72_2: R72.2 U13.5(IN_B+)
NetR77_1: R77.1 U14.1(VOUT_A) U14.2(IN_A-)
NetR81_2: R81.2 R83.1 U15.3(IN+)
NetR82_2: R82.2 U15.6(IN-)
NetR84_2: R84.2 U15.5(IN+)
NetR85_1: R85.1 U14.6(IN_B-) U14.7(VOUT_B)
NetTP5_1: TP5.1 U11.5(VREF)

Not connected (* = marked no-connect by the designer): U15 7(OUT)

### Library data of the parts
C46 C58 C61 C71 C72 C83 = GRM1555C1H4R7WA01D: CAP, CERM, 4.7 pF, 50 V, +/- 1%, C0G/NP0, 0402; Manufacturer: MuRata; Polarized: N; CompType: Capacitor; Value: 4.7pF; U/M: EA; Cap_F: 0.0000000000047; Tolerance_%: 1; Value1: Unknown; VDC_V: 50; Value2: 50V; TaMin_C: -55; TaMax_C: 125
C47 C49 C50 C59 C60 C62 C73-C75 = GRM188R71C104KA01D: CAP, CERM, 0.1 µF, 16 V, +/- 10%, X7R, 0603; Manufacturer: MuRata; Polarized: N; CompType: Capacitor; Value: 0.1uF; U/M: EA; Cap_F: 0.0000001; Tolerance_%: 10; Value1: Unknown; VDC_V: 16; Value2: 16V; TaMin_C: -55; TaMax_C: 125
C48 C54 C63 C67 C79 = GRM1885C1H222JA01D: CAP, CERM, 2200 pF, 50 V, +/- 5%, C0G/NP0, 0603; Manufacturer: MuRata; Polarized: N; CompType: Capacitor; Value: 2200pF; U/M: EA; Cap_F: 0.0000000022; Tolerance_%: 5; Value1: Unknown; VDC_V: 50; Value2: 50V; TaMin_C: -55; TaMax_C: 125
C51 C57 C64 C70 C76 C82 = GRM155R71C104KA88D: CAP, CERM, 0.1 µF, 16 V, +/- 10%, X7R, 0402; Manufacturer: MuRata; Polarized: N; CompType: Capacitor; Value: 0.1uF; U/M: EA; Cap_F: 0.0000001; Tolerance_%: 10; Value1: Unknown; VDC_V: 16; Value2: 16V; TaMin_C: -55; TaMax_C: 125
C52 C56 C65 C69 C77 C81 = GRM1555C1E470JA01D: CAP, CERM, 47 pF, 25 V, +/- 5%, C0G/NP0, 0402; Manufacturer: MuRata; Polarized: N; CompType: Capacitor; Value: 47pF; U/M: EA; Cap_F: 0.000000000047; Tolerance_%: 5; Value1: Unknown; VDC_V: 25; Value2: 25V; TaMin_C: -55; TaMax_C: 125
C53 C55 C66 C68 C78 C80 = GRM1535C1H101JDD5D: CAP, CERM, 100 pF, 50 V, +/- 5%, C0G/NP0, 0402; Manufacturer: MuRata; Polarized: N; CompType: Capacitor; Value: 100pF; U/M: EA; Cap_F: 0.0000000001; Tolerance_%: 5; Value1: Unknown; VDC_V: 50; Value2: 50V; TaMin_C: -55; TaMax_C: 125
D17-D19 = ZHCS350TA: Diode, Schottky, 40 V, 0.35 A, SOD-523; Manufacturer: Diodes Inc.; U/M: EA; Vf_V: 0.65; Value: 40V; Value1: 0.35A; Value2: 0.65V; Io_A: 0.35; Vr_V: 40
R41 R57 = CRCW0402100RJNED: RES, 100, 5%, 0.063 W, 0402; Manufacturer: Vishay-Dale; CompType: Resistor; Value: 100; Value_Code: 100R; Tolerance_%: 5; Power_W: 0.063; Value2: 0.063W; VDC_V: 50; TempCo: 200 ppm/C; EIA_Code: E24; U/M: EA
R42 R73 = CRCW04021R00JNED: RES, 1.0, 5%, 0.063 W, 0402; Manufacturer: Vishay-Dale; CompType: Resistor; Value: 1.0; Res_ohm: 1; Value_Code: 1R00; Tolerance_%: 5; Power_W: 0.063; Value2: 0.063W; VDC_V: 50; TempCo: 200 ppm/C; EIA_Code: E24; U/M: EA
R43 R55 R58 R70 R74 R88 = ERA-2AEB8451X: RES, 8.45 k, 0.1%, 0.063 W, 0402; Manufacturer: Panasonic; CompType: Resistor; Value: 8.45k; Res_ohm: 8450; Value_Code: 8k45; Tolerance_%: 0.1; Power_W: 0.063; Value2: 0.063W; VDC_V: 50; TempCo: 25 ppm/C; EIA_Code: E192; U/M: EA
R44 R48 R59 R63 R75 R79 = CRCW040210R0FKED: RES, 10.0, 1%, 0.063 W, 0402; Manufacturer: Vishay-Dale; CompType: Resistor; Value: 10.0; Res_ohm: 10; Value_Code: 10R0; Tolerance_%: 1; Power_W: 0.063; Value2: 0.063W; VDC_V: 50; TempCo: 100 ppm/C; EIA_Code: E96; U/M: EA
R45 R54 R60 R69 R76 R87 = CRCW0402220RJNED: RES, 220, 5%, 0.063 W, 0402; Manufacturer: Vishay-Dale; CompType: Resistor; Value: 220; Value_Code: 220R; Tolerance_%: 5; Power_W: 0.063; Value2: 0.063W; VDC_V: 50; TempCo: 200 ppm/C; EIA_Code: E24; U/M: EA
R46 R52 R61 R67 R77 R85 = CRCW0402332RFKED: RES, 332, 1%, 0.063 W, 0402; Manufacturer: Vishay-Dale; CompType: Resistor; Value: 332; Value_Code: 332R; Tolerance_%: 1; Power_W: 0.063; Value2: 0.063W; VDC_V: 50; TempCo: 100 ppm/C; EIA_Code: E96; U/M: EA
R47 R53 R62 R68 R78 R86 = ERA-2AEB4751X: RES, 4.75 k, 0.1%, 0.063 W, 0402; Manufacturer: Panasonic; CompType: Resistor; Value: 4.75k; Res_ohm: 4750; Value_Code: 4k75; Tolerance_%: 0.1; Power_W: 0.063; Value2: 0.063W; VDC_V: 50; TempCo: 25 ppm/C; EIA_Code: E192; U/M: EA
R49 R64 R80 = CRCW040220R0FKED: RES, 20.0, 1%, 0.063 W, 0402; Manufacturer: Vishay-Dale; CompType: Resistor; Value: 20.0; Res_ohm: 20; Value_Code: 20R0; Tolerance_%: 1; Power_W: 0.063; Value2: 0.063W; VDC_V: 50; TempCo: 100 ppm/C; EIA_Code: E96; U/M: EA
R50 R65 R81 = CRCW040226K7FKED: RES, 26.7 k, 1%, 0.063 W, 0402; Manufacturer: Vishay-Dale; CompType: Resistor; Value: 26.7k; Res_ohm: 26700; Value_Code: 26k7; Tolerance_%: 1; Power_W: 0.063; Value2: 0.063W; VDC_V: 50; TempCo: 100 ppm/C; EIA_Code: E96; U/M: EA
R51 R66 R83 = CRCW0402549KFKED: RES, 549 k, 1%, 0.063 W, 0402; Manufacturer: Vishay-Dale; CompType: Resistor; Value: 549k; Res_ohm: 549000; Tolerance_%: 1; Power_W: 0.063; Value2: 0.063W; VDC_V: 50; TempCo: 100 ppm/C; EIA_Code: E96; U/M: EA
R56 = CRCW04020000Z0ED: as R14 on sheet TIDA-00176_PS
R71 R72 R82 R84 = CRCW04021K00FKED: RES, 1.00 k, 1%, 0.063 W, 0402; Manufacturer: Vishay-Dale; CompType: Resistor; Value: 1.00k; Res_ohm: 1000; Value_Code: 1k00; Tolerance_%: 1; Power_W: 0.063; Value2: 0.063W; VDC_V: 50; TempCo: 100 ppm/C; EIA_Code: E96; U/M: EA
TP5 TP6 = 5002: Test Point, Miniature, White, TH; Manufacturer: Keystone; CompType: Test Point Loop; U/M: EA
U8 U12 U14 = OPA2365AIDR: 50 MHz, Low-Noise Single-Supply Rail-to-Rail Operational Amplifier, 2.2 to 5.5 V, -40 to 125 degC, 8-pin SOIC (D0008A), Green (RoHS & no Sb/Br); Manufacturer: Texas Instruments; Alternate Manufacturer: None; Alternate PartNumber: Equivalent; CMRR(Min)(dB): 100; IIB(Max)(pA): 10; Iq per channel(Max)(mA): 5; Number of Channels: 2; Offset Drift(Typ)(uV/C): 1; Slew Rate(Typ)(V/us): 25; Sub Family: High Speed Amplifier (>=50MHz), Low Input Bias Current Amp (<=10pA), Low Offset Voltage Amplifier (<=500uV), Low Supply Voltage Amplifier (<=2.7V); Total Supply Voltage(Max)(+5V is 5, +/-5V is 10): 5.5; Total Supply Voltage(Min)(+5V is 5, +/-5V is 10): 2.2; Vio (25C)(Max)(mV): 0.2
U9 U15 = TLV3202AID: 40-ns, microPOWER, Push-Pull Output Comparators, D0008A; Manufacturer: Texas Instruments; CompType: IC; U/M: EA
U10 U13 = OPA2365AIDR: 50 MHz, Low-Noise Single-Supply Rail-to-Rail Operational Amplifier, 2.2 to 5.5 V, -40 to 125 degC, 8-pin SOIC (D0008A), Green (RoHS & no Sb/Br); Manufacturer: Texas Instruments; Alternate Manufacturer: None; Alternate PartNumber: Equivalent; Iq per channel(Max)(mA): 5; Number of Channels: 2; Slew Rate(Typ)(V/us): 25; Sub Family: High Speed Amplifier (>=50MHz), Low Input Bias Current Amp (<=10pA), Low Offset Voltage Amplifier (<=500uV), Low Supply Voltage Amplifier (<=2.7V); CMRR(Min)(dB): 100; IIB(Max)(pA): 10; Offset Drift(Typ)(uV/C): 1; Total Supply Voltage(Max)(+5V is 5, +/-5V is 10): 5.5; Total Supply Voltage(Min)(+5V is 5, +/-5V is 10): 2.2; Vio (25C)(Max)(mV): 0.2
U11 = REF2033AIDDCR: Low-Drift, Low-Power, Dual-Output, VREF and VREF / 2 Voltage References, DDC0005A; Alternate PartNumber: REF2033AIDDCT; Manufacturer: Texas Instruments; SymbolCreator: a0799628; CompType: IC; U/M: EA

## Sheet TIDA-00176_SCLS.SchDoc
size 431 x 279 mm; Date: Not shown in title block; ApprovedBy: Not shown in title block; CheckedBy: Not shown in title block; Author: Not shown in title block; CompanyName: Not shown in title block; Engineer: Not shown in title block; Organization: Not shown in title block; Address1: Not shown in title block; Address2: Not shown in title block; Address3: Not shown in title block; Address4: Not shown in title block; DocumentNumber: 1; Revision: Use project parameter SCH_Rev; SheetNumber: 2; SheetTotal: 3; PageSetup: Record=PageOptions¦CenterHorizontal=True¦CenterVertical=True¦PrintScale=0.68¦XCorrection=1.00¦YCorrection=1.00¦PrintKind=0¦BorderSize=5000000¦LeftOffset=0¦BottomOffset=0¦Orientation=2¦PaperLength=2970¦PaperWidth=2100¦Scale=100¦PaperSource=7¦PrintQuality=600¦MediaType=1¦DitherType=10¦PrintScaleMode=1¦PaperKind=A4¦PaperIndex=9
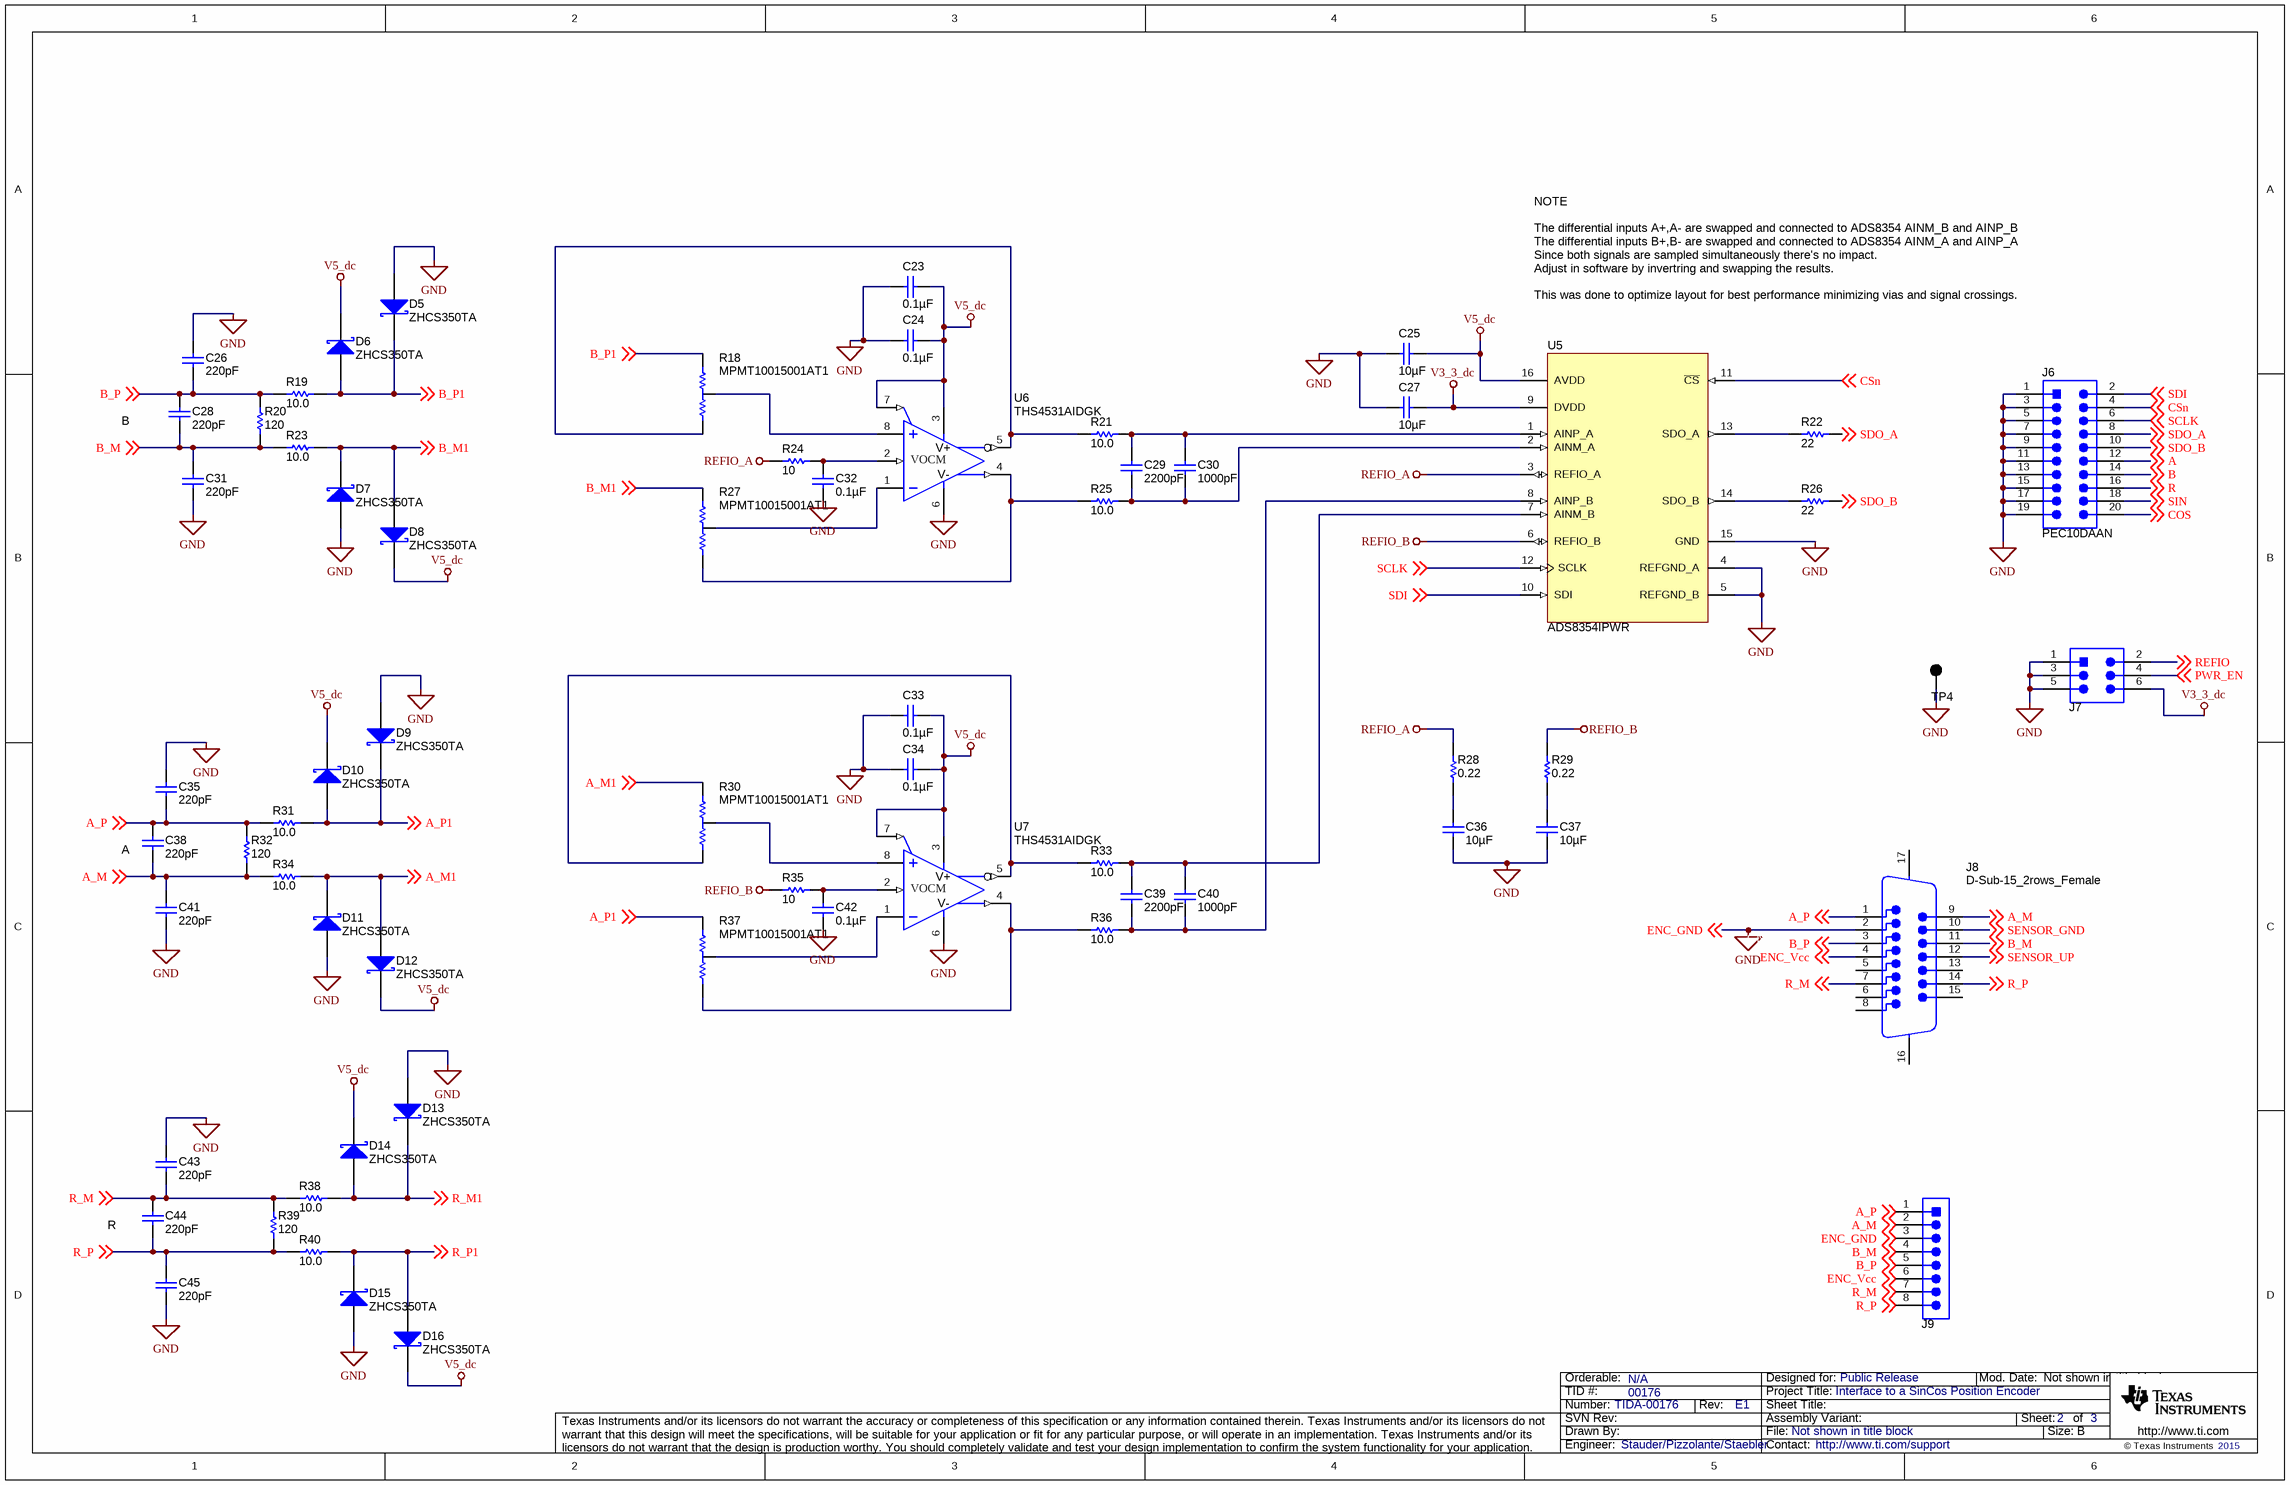
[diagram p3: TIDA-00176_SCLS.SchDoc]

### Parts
C23  ValueDisplayed: 0.1µF  [0603]  (hidden comment: GRM188R71C104KA01D)
C24  ValueDisplayed: 0.1µF  [0603_HV]  (hidden comment: GRM188R71C104KA01D)
C25  ValueDisplayed: 10µF  [0805_140]  (hidden comment: CL21B106KOQNNNE)
C26  ValueDisplayed: 220pF  [0402]  (hidden comment: GRM1555C1H221JA01D)
C27  ValueDisplayed: 10µF  [0805_140]  (hidden comment: CL21B106KOQNNNE)
C28  ValueDisplayed: 220pF  [0402]  (hidden comment: GRM1555C1H221JA01D)
C29  ValueDisplayed: 2200pF  [0603]  (hidden comment: GRM1885C1H222JA01D)
C30  ValueDisplayed: 1000pF  [0402]  (hidden comment: GRM1555C1H102JA01D)
C31  ValueDisplayed: 220pF  [0402]  (hidden comment: GRM1555C1H221JA01D)
C32  ValueDisplayed: 0.1µF  [0402]  (hidden comment: GRM155R71C104KA88D)
C33  ValueDisplayed: 0.1µF  [0603]  (hidden comment: GRM188R71C104KA01D)
C34  ValueDisplayed: 0.1µF  [0603_HV]  (hidden comment: GRM188R71C104KA01D)
C35  ValueDisplayed: 220pF  [0402]  (hidden comment: GRM1555C1H221JA01D)
C36  ValueDisplayed: 10µF  [0805_140]  (hidden comment: GRM21BR71A106KE51K)
C37  ValueDisplayed: 10µF  [0805_140]  (hidden comment: GRM21BR71A106KE51K)
C38  ValueDisplayed: 220pF  [0402]  (hidden comment: GRM1555C1H221JA01D)
C39  ValueDisplayed: 2200pF  [0603]  (hidden comment: GRM1885C1H222JA01D)
C40  ValueDisplayed: 1000pF  [0402]  (hidden comment: GRM1555C1H102JA01D)
C41  ValueDisplayed: 220pF  [0402]  (hidden comment: GRM1555C1H221JA01D)
C42  ValueDisplayed: 0.1µF  [0402]  (hidden comment: GRM155R71C104KA88D)
C43  ValueDisplayed: 220pF  [0402]  (hidden comment: GRM1555C1H221JA01D)
C44  ValueDisplayed: 220pF  [0402]  (hidden comment: GRM1555C1H221JA01D)
C45  ValueDisplayed: 220pF  [0402]  (hidden comment: GRM1555C1H221JA01D)
D5  ZHCS350TA  [SOD-523]
D6  ZHCS350TA  [SOD-523]
D7  ZHCS350TA  [SOD-523]
D8  ZHCS350TA  [SOD-523]
D9  ZHCS350TA  [SOD-523]
D10  ZHCS350TA  [SOD-523]
D11  ZHCS350TA  [SOD-523]
D12  ZHCS350TA  [SOD-523]
D13  ZHCS350TA  [SOD-523]
D14  ZHCS350TA  [SOD-523]
D15  ZHCS350TA  [SOD-523]
D16  ZHCS350TA  [SOD-523]
J6  PEC10DAAN  [SULLINS_PEC10DAAN]
J7  PEC03DAAN  [SULLINS_PEC03DAAN]  (value not drawn)
J8  D-Sub-15_2rows_Female  [Harting_09 66 252 6610]
J9  800-10-008-10-001000  [Mill-Max_800-10-008-10-001000]  (value not drawn)
R18  MPMT10015001AT1  [SOT-23M]
R19  ValueDisplayed: 10.0  [0402]  (hidden comment: CRCW040210R0FKED)
R20  ValueDisplayed: 120  [0805_HV]  (hidden comment: ESR10EZPF1200)
R21  ValueDisplayed: 10.0  [0402]  (hidden comment: CRCW040210R0FKED)
R22  ValueDisplayed: 22  [0402]  (hidden comment: CRCW040222R0JNED)
R23  ValueDisplayed: 10.0  [0402]  (hidden comment: CRCW040210R0FKED)
R24  ValueDisplayed: 10  [0402]  (hidden comment: CRCW040210R0JNED)
R25  ValueDisplayed: 10.0  [0402]  (hidden comment: CRCW040210R0FKED)
R26  ValueDisplayed: 22  [0402]  (hidden comment: CRCW040222R0JNED)
R27  MPMT10015001AT1  [SOT-23M]
R28  ValueDisplayed: 0.22  [0603]  (hidden comment: ERJ-3RQFR22V)
R29  ValueDisplayed: 0.22  [0603]  (hidden comment: ERJ-3RQFR22V)
R30  MPMT10015001AT1  [SOT-23M]
R31  ValueDisplayed: 10.0  [0402]  (hidden comment: CRCW040210R0FKED)
R32  ValueDisplayed: 120  [0805_HV]  (hidden comment: ESR10EZPF1200)
R33  ValueDisplayed: 10.0  [0402]  (hidden comment: CRCW040210R0FKED)
R34  ValueDisplayed: 10.0  [0402]  (hidden comment: CRCW040210R0FKED)
R35  ValueDisplayed: 10  [0402]  (hidden comment: CRCW040210R0JNED)
R36  ValueDisplayed: 10.0  [0402]  (hidden comment: CRCW040210R0FKED)
R37  MPMT10015001AT1  [SOT-23M]
R38  ValueDisplayed: 10.0  [0402]  (hidden comment: CRCW040210R0FKED)
R39  ValueDisplayed: 120  [0805_HV]  (hidden comment: ESR10EZPF1200)
R40  ValueDisplayed: 10.0  [0402]  (hidden comment: CRCW040210R0FKED)
TP4  5001  [Keystone5001]  (value not drawn)
U5  ADS8354IPWR  [PW0016A_N]
U6  THS4531AIDGK  [DGK0008A_N]
U7  THS4531AIDGK  [DGK0008A_N]

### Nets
GND: C23.1 C24.1 C25.1 C26.1 C27.1 C31.2 C32.2 C33.1 C34.1 C35.1 C36.1 C37.2 C41.2 C42.2 C43.2 C45.1 D5.2(A) D7.2(A) D9.2(A) D11.2(A) D13.2(A) D15.2(A) J6.1 J6.3 J6.5 J6.7 J6.9 J6.11 J6.13 J6.15 J6.17 J6.19 J7.1 J7.3 J7.5 J8.2 J9.3 TP4.1 U5.4(REFGND_A) U5.5(REFGND_B) U5.15(GND) U6.6(VS-) U7.6(VS-) ; off-sheet ENC_GND  [also labelled ENC_GND]
REFIO_A: R24.1 R28.2 U5.3(REFIO_A)
REFIO_B: R29.2 R35.1 U5.6(REFIO_B)
V3_3_dc: C27.2 J7.6 U5.9(DVDD)
V5_dc: C23.2 C24.2 C25.2 C33.2 C34.2 D6.1(K) D8.1(K) D10.1(K) D12.1(K) D14.1(K) D16.1(K) U5.16(AVDD) U6.3(VS+) U6.7(~{PD}) U7.3(VS+) U7.7(~{PD})
A: J6.12 ; off-sheet A
A_M: C38.2 C41.1 J8.9 J9.2 R32.1 R34.1 ; off-sheet A_M
A_M1: D11.1(K) D12.2(A) R30.1 R34.2 ; off-sheet A_M1
A_P: C35.2 C38.1 J8.1 J9.1 R31.1 R32.2 ; off-sheet A_P
A_P1: D9.1(K) D10.2(A) R31.2 R37.1 ; off-sheet A_P1
B: J6.14 ; off-sheet B
B_M: C28.2 C31.1 J8.11 J9.4 R20.1 R23.1 ; off-sheet B_M
B_M1: D7.1(K) D8.2(A) R23.2 R27.1 ; off-sheet B_M1
B_P: C26.2 C28.1 J8.3 J9.5 R19.1 R20.2 ; off-sheet B_P
B_P1: D5.1(K) D6.2(A) R18.1 R19.2 ; off-sheet B_P1
COS: J6.20 ; off-sheet COS
CSn: J6.4 U5.11(~{CS}) ; off-sheet CSn
ENC_Vcc: J8.4 J9.6 ; off-sheet ENC_Vcc
PWR_EN: J7.4 ; off-sheet PWR_EN
R: J6.16 ; off-sheet R
R_M: C43.1 C44.2 J8.7 J9.7 R38.1 R39.2 ; off-sheet R_M
R_M1: D13.1(K) D14.2(A) R38.2 ; off-sheet R_M1
R_P: C44.1 C45.2 J8.14 J9.8 R39.1 R40.1 ; off-sheet R_P
R_P1: D15.1(K) D16.2(A) R40.2 ; off-sheet R_P1
REFIO: J7.2 ; off-sheet REFIO
SCLK: J6.6 U5.12(SCLK) ; off-sheet SCLK
SDI: J6.2 U5.10(SDI) ; off-sheet SDI
SDO_A: J6.8 R22.2 ; off-sheet SDO_A
SDO_B: J6.10 R26.2 ; off-sheet SDO_B
SENSOR_GND: J8.10 ; off-sheet SENSOR_GND
SENSOR_UP: J8.12 ; off-sheet SENSOR_UP
SIN: J6.18 ; off-sheet SIN
NetC29_1: C29.1 C30.1 R21.2 U5.1(AINP_A)
NetC29_2: C29.2 C30.2 R25.2 U5.2(AINM_A)
NetC32_1: C32.1 R24.2 U6.2(VOCM)
NetC36_2: C36.2 R28.1
NetC37_1: C37.1 R29.1
NetC39_1: C39.1 C40.1 R33.2 U5.7(AINM_B)
NetC39_2: C39.2 C40.2 R36.2 U5.8(AINP_B)
NetC42_1: C42.1 R35.2 U7.2(VOCM)
NetR18_2: R18.2 R21.1 U6.5(VOUT-)
NetR18_3: R18.3 U6.8(VIN+)
NetR22_1: R22.1 U5.13(SDO_A)
NetR25_1: R25.1 R27.2 U6.4(VOUT+)
NetR26_1: R26.1 U5.14(SDO_B)
NetR27_3: R27.3 U6.1(VIN-)
NetR30_2: R30.2 R33.1 U7.5(VOUT-)
NetR30_3: R30.3 U7.8(VIN+)
NetR36_1: R36.1 R37.2 U7.4(VOUT+)
NetR37_3: R37.3 U7.1(VIN-)

Not connected (* = marked no-connect by the designer): J8 5 6 8 13 15 16(MH1) 17(MH2)

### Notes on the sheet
- NOTE
  The differential inputs A+,A- are swapped and connected to ADS8354 AINM_B and AINP_B
  The differential inputs B+,B- are swapped and connected to ADS8354 AINM_A and AINP_A
  Since both signals are sampled simultaneously there's no impact.
  Adjust in software by invertring and swapping the results.
  This was done to optimize layout for best performance minimizing vias and signal crossings.
- B
- (near C38) A
- (near C44) R

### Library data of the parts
C23 C33 = GRM188R71C104KA01D: as C47 on sheet TIDA-00176_SCHS
C24 C34 = GRM188R71C104KA01D: CAP, CERM, 0.1 µF, 16 V, +/- 10%, X7R, 0603; Manufacturer: MuRata; Polarized: N; CompType: Capacitor; Value: 0.1uF; U/M: EA; Cap_F: 0.0000001; Tolerance_%: 10; Value1: Unknown; VDC_V: 16; Value2: 16V; TaMin_C: -55; TaMax_C: 125; Cap_Case: 0603
C25 C27 = CL21B106KOQNNNE: CAP, CERM, 10 µF, 16 V, +/- 10%, X7R, 0805_140; Manufacturer: Samsung; Polarized: N; CompType: Capacitor; Value: 10uF; U/M: EA; Cap_F: 0.00001; Tolerance_%: 10; Value1: Unknown; VDC_V: 16; Value2: 16V; TaMin_C: -55; TaMax_C: 125; Cap_Case: 0805
C26 C28 C31 C35 C38 C41 C43-C45 = GRM1555C1H221JA01D: CAP, CERM, 220 pF, 50 V, +/- 5%, C0G/NP0, 0402; Manufacturer: MuRata; Polarized: N; CompType: Capacitor; Value: 220pF; U/M: EA; Cap_F: 0.00000000022; Tolerance_%: 5; Value1: Unknown; VDC_V: 50; Value2: 50V; TaMin_C: -55; TaMax_C: 125
C29 C39 = GRM1885C1H222JA01D: as C48 on sheet TIDA-00176_SCHS
C30 C40 = GRM1555C1H102JA01D: CAP, CERM, 1000 pF, 50 V, +/- 5%, C0G/NP0, 0402; Manufacturer: MuRata; Polarized: N; CompType: Capacitor; Value: 1000pF; U/M: EA; Cap_F: 0.000000001; Tolerance_%: 5; Value1: Unknown; VDC_V: 50; Value2: 50V; TaMin_C: -55; TaMax_C: 125
C32 C42 = GRM155R71C104KA88D: as C51 on sheet TIDA-00176_SCHS
C36 C37 = GRM21BR71A106KE51K: CAP, CERM, 10 µF, 10 V, +/- 10%, X7R, 0805_140; Manufacturer: MuRata; Polarized: N; CompType: Capacitor; Value: 10uF; U/M: EA; Cap_F: 0.00001; Tolerance_%: 10; Value1: Unknown; Value2: 10V; TaMin_C: -55; TaMax_C: 125; Cap_Case: 0805
D5-D16 = ZHCS350TA: as D17 on sheet TIDA-00176_SCHS
J6 = PEC10DAAN: Header, 100mil, 10x2, TH; Manufacturer: Sullins Connector Solutions; SymbolCreator: a0412235; U/M: EA
J7 = PEC03DAAN: Header, 100mil, 3x2, Tin, TH; Manufacturer: Sullins Connector Solutions; SymbolCreator: a0412235; U/M: EA
J8 = 09 66 252 6610: D-Sub-15, 17Pos, TH; Manufacturer: Harting; SymbolCreator: x0208325; CompType: D-Sub; U/M: EA
J9 = 800-10-008-10-001000: Header, 100mil, 8x1, TH; Manufacturer: Mill-Max; SymbolCreator: a0411947; U/M: EA
R18 R27 R30 R37 = MPMT10015001AT1: Resistor Networks, 1K ohm, 5K ohm, SMD; Manufacturer: Vishay-Dale; SymbolCreator: Altium; Value: 1000Ohm, 4000Ohm
R19 R21 R23 R25 R31 R33 R34 R36 R38 R40 = CRCW040210R0FKED: as R44 on sheet TIDA-00176_SCHS
R20 R32 R39 = ESR10EZPF1200: RES, 120, 1%, 0.4 W, 0805; Manufacturer: Rohm; CompType: Resistor; Value: 120; Value_Code: 120R; Tolerance_%: 1; Power_W: 0.4; Value2: 0.4W; VDC_V: 150; TempCo: 100 ppm/C; U/M: EA
R22 R26 = CRCW040222R0JNED: RES, 22, 5%, 0.063 W, 0402; Manufacturer: Vishay-Dale; CompType: Resistor; Value: 22; Value_Code: 22R0; Tolerance_%: 5; Power_W: 0.063; Value2: 0.063W; VDC_V: 50; TempCo: 200 ppm/C; EIA_Code: E24; U/M: EA
R24 R35 = CRCW040210R0JNED: RES, 10, 5%, 0.063 W, 0402; Manufacturer: Vishay-Dale; CompType: Resistor; Value: 10; Value_Code: 10R0; Tolerance_%: 5; Power_W: 0.063; Value2: 0.063W; VDC_V: 50; TempCo: 200 ppm/C; EIA_Code: E24; U/M: EA
R28 R29 = ERJ-3RQFR22V: RES, 0.22, 1%, 0.1 W, 0603; Manufacturer: Panasonic; CompType: Resistor; Value: 0.22; Value_Code: R220; Tolerance_%: 1; Power_W: 0.1; Value2: 0.1W; TempCo: 300 ppm/C; EIA_Code: E96; U/M: EA
TP4 = 5001: as TP1 on sheet TIDA-00176_PS
U5 = ADS8354IPWR: Dual, High-Speed, 16-, 14-, and 12-Bit, Simultaneous-Sampling, Analog-to-Digital Converters, PW0016A; Manufacturer: Texas Instruments; SymbolCreator: Altium; CompType: IC; U/M: EA
U6 U7 = THS4531AIDGK: Ultra Low Power, Rail-to-Rail Output, Fully-Differential Amplifier, DGK0008A; Manufacturer: Texas Instruments; SymbolCreator: Altium; CompType: IC; U/M: EA

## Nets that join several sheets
GND: TIDA-00176_PS (40 pins), TIDA-00176_SCHS (42 pins), TIDA-00176_SCLS (43 pins)
V3_3_dc: TIDA-00176_PS (R17.2), TIDA-00176_SCHS (5 pins), TIDA-00176_SCLS (C27.2 J7.6 U5.9)
V5_dc: TIDA-00176_PS (R14.2), TIDA-00176_SCHS (13 pins), TIDA-00176_SCLS (16 pins)
A: TIDA-00176_SCHS (R51.2 U9.1), TIDA-00176_SCLS (J6.12)
A_M1: TIDA-00176_SCHS (R45.1), TIDA-00176_SCLS (D11.1 D12.2 R30.1 R34.2)
A_P1: TIDA-00176_SCHS (R54.1), TIDA-00176_SCLS (D9.1 D10.2 R31.2 R37.1)
B: TIDA-00176_SCHS (R66.2 U9.7), TIDA-00176_SCLS (J6.14)
B_M1: TIDA-00176_SCHS (R60.1), TIDA-00176_SCLS (D7.1 D8.2 R23.2 R27.1)
B_P1: TIDA-00176_SCHS (R69.1), TIDA-00176_SCLS (D5.1 D6.2 R18.1 R19.2)
COS: TIDA-00176_SCHS (C63.1 R57.2), TIDA-00176_SCLS (J6.20)
ENC_Vcc: TIDA-00176_PS (J4.2 R12.2), TIDA-00176_SCLS (J8.4 J9.6)
PWR_EN: TIDA-00176_PS (U2.4), TIDA-00176_SCLS (J7.4)
R: TIDA-00176_SCHS (R83.2 U15.1), TIDA-00176_SCLS (J6.16)
R_M1: TIDA-00176_SCHS (R76.1), TIDA-00176_SCLS (D13.1 D14.2 R38.2)
R_P1: TIDA-00176_SCHS (R87.1), TIDA-00176_SCLS (D15.1 D16.2 R40.2)
REFIO: TIDA-00176_SCHS (13 pins), TIDA-00176_SCLS (J7.2)
SIN: TIDA-00176_SCHS (C48.1 R41.2), TIDA-00176_SCLS (J6.18)

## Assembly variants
Complete: not fitted FID1 FID2 FID3
TIDA-00176_REVE1_production: not fitted C4 C11 C30 C40 C52 C56 C65 C69 C77 C81 FID1 FID2 FID3 R4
